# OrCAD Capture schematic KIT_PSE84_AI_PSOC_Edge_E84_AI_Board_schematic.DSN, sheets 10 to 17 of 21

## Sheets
10 09. On board sensors: size A4
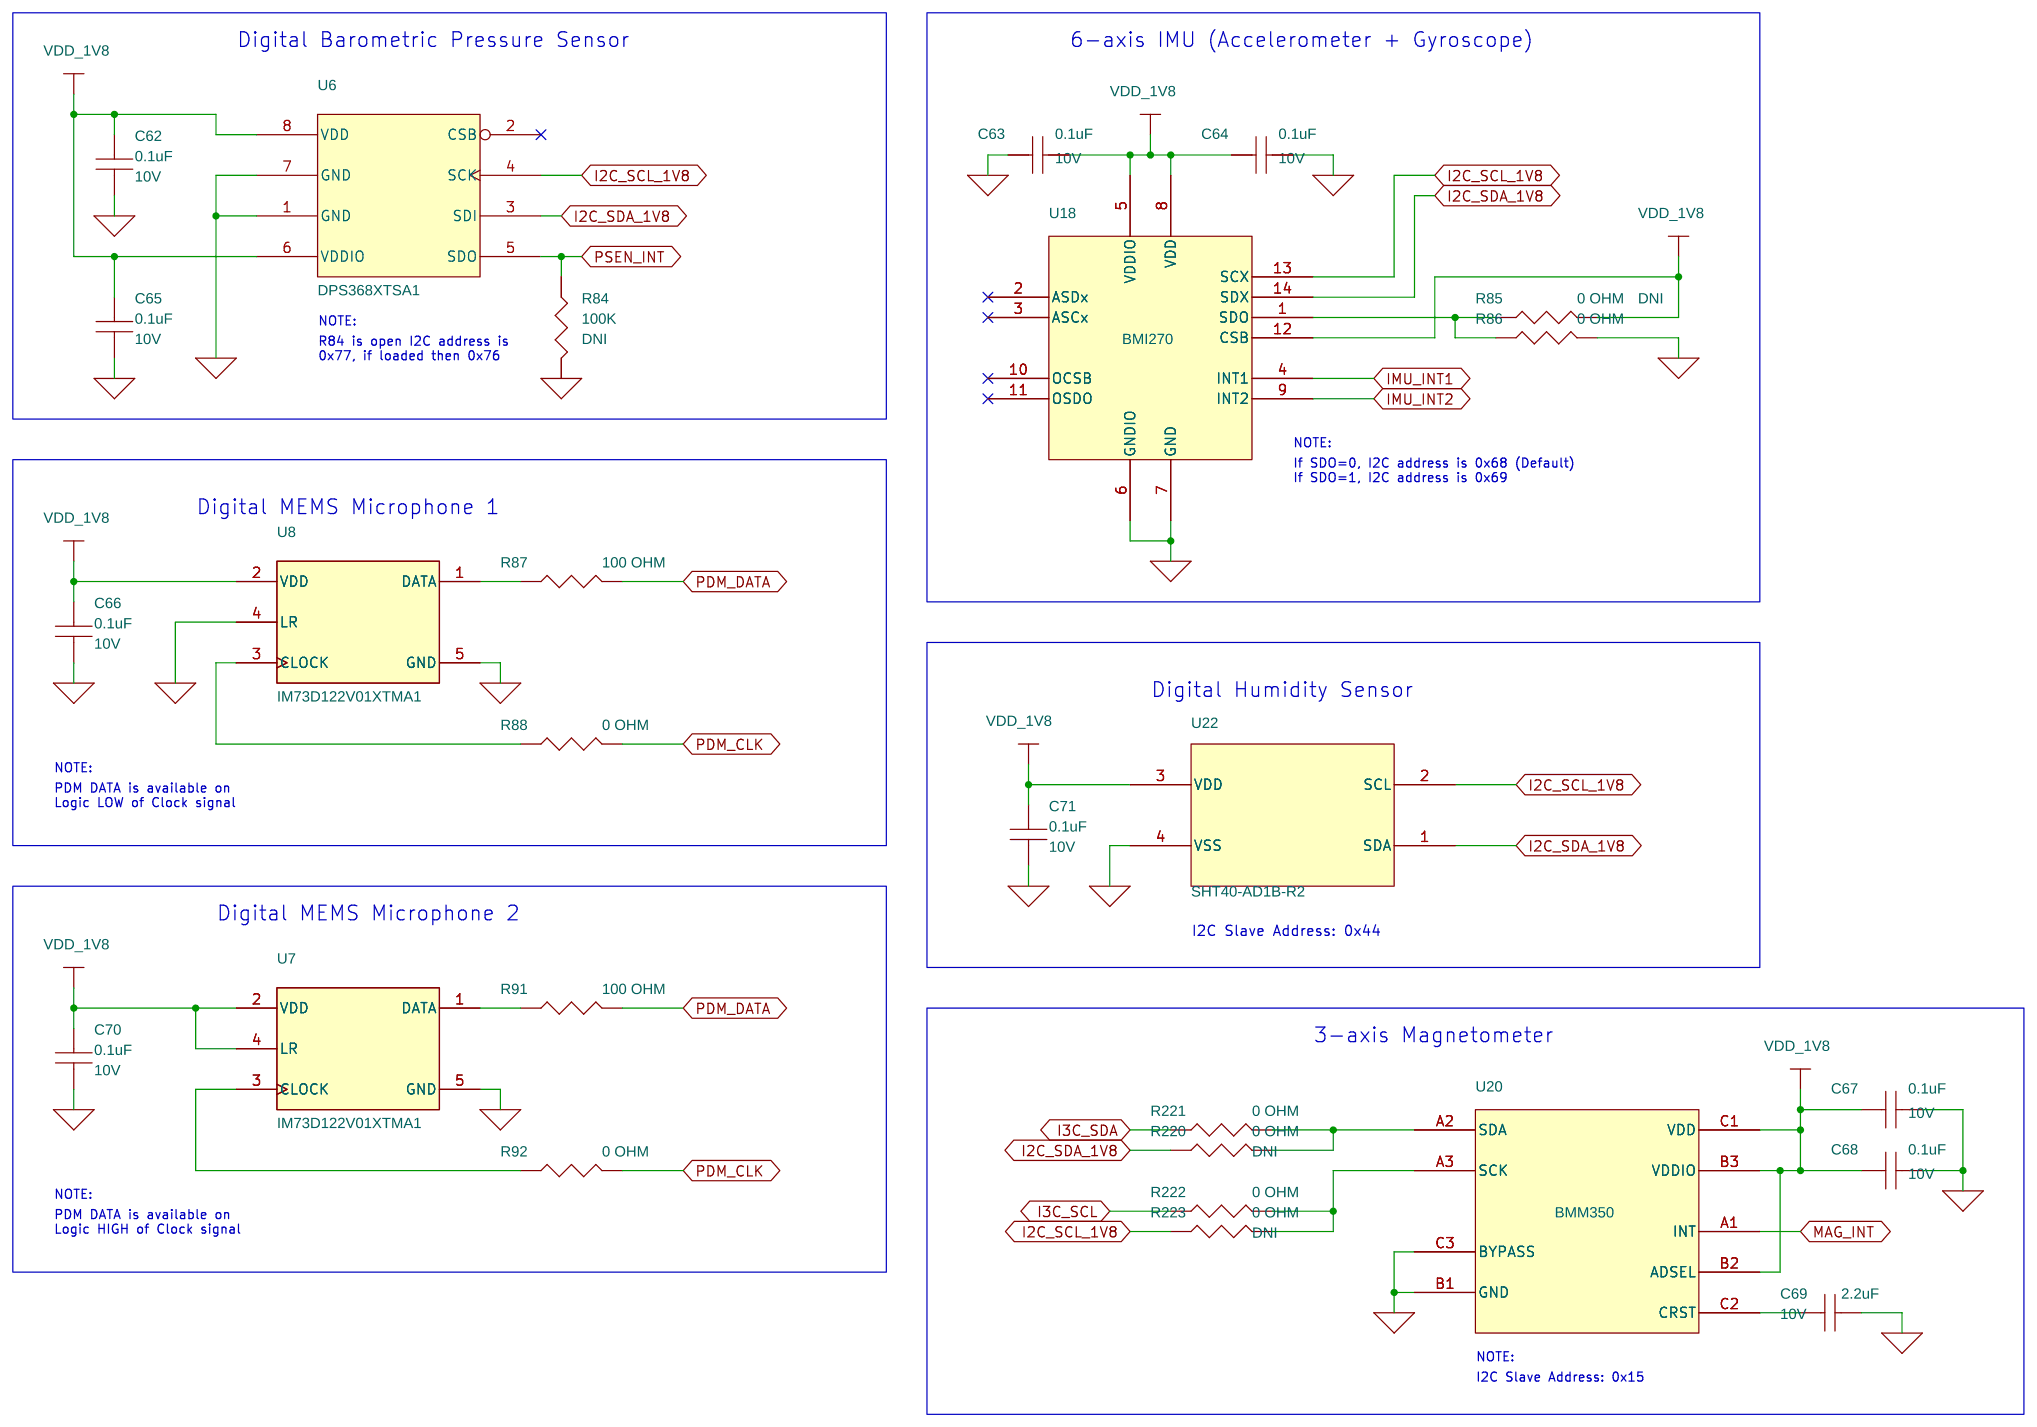
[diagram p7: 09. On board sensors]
11 10. RADAR Sensor interface: size A4
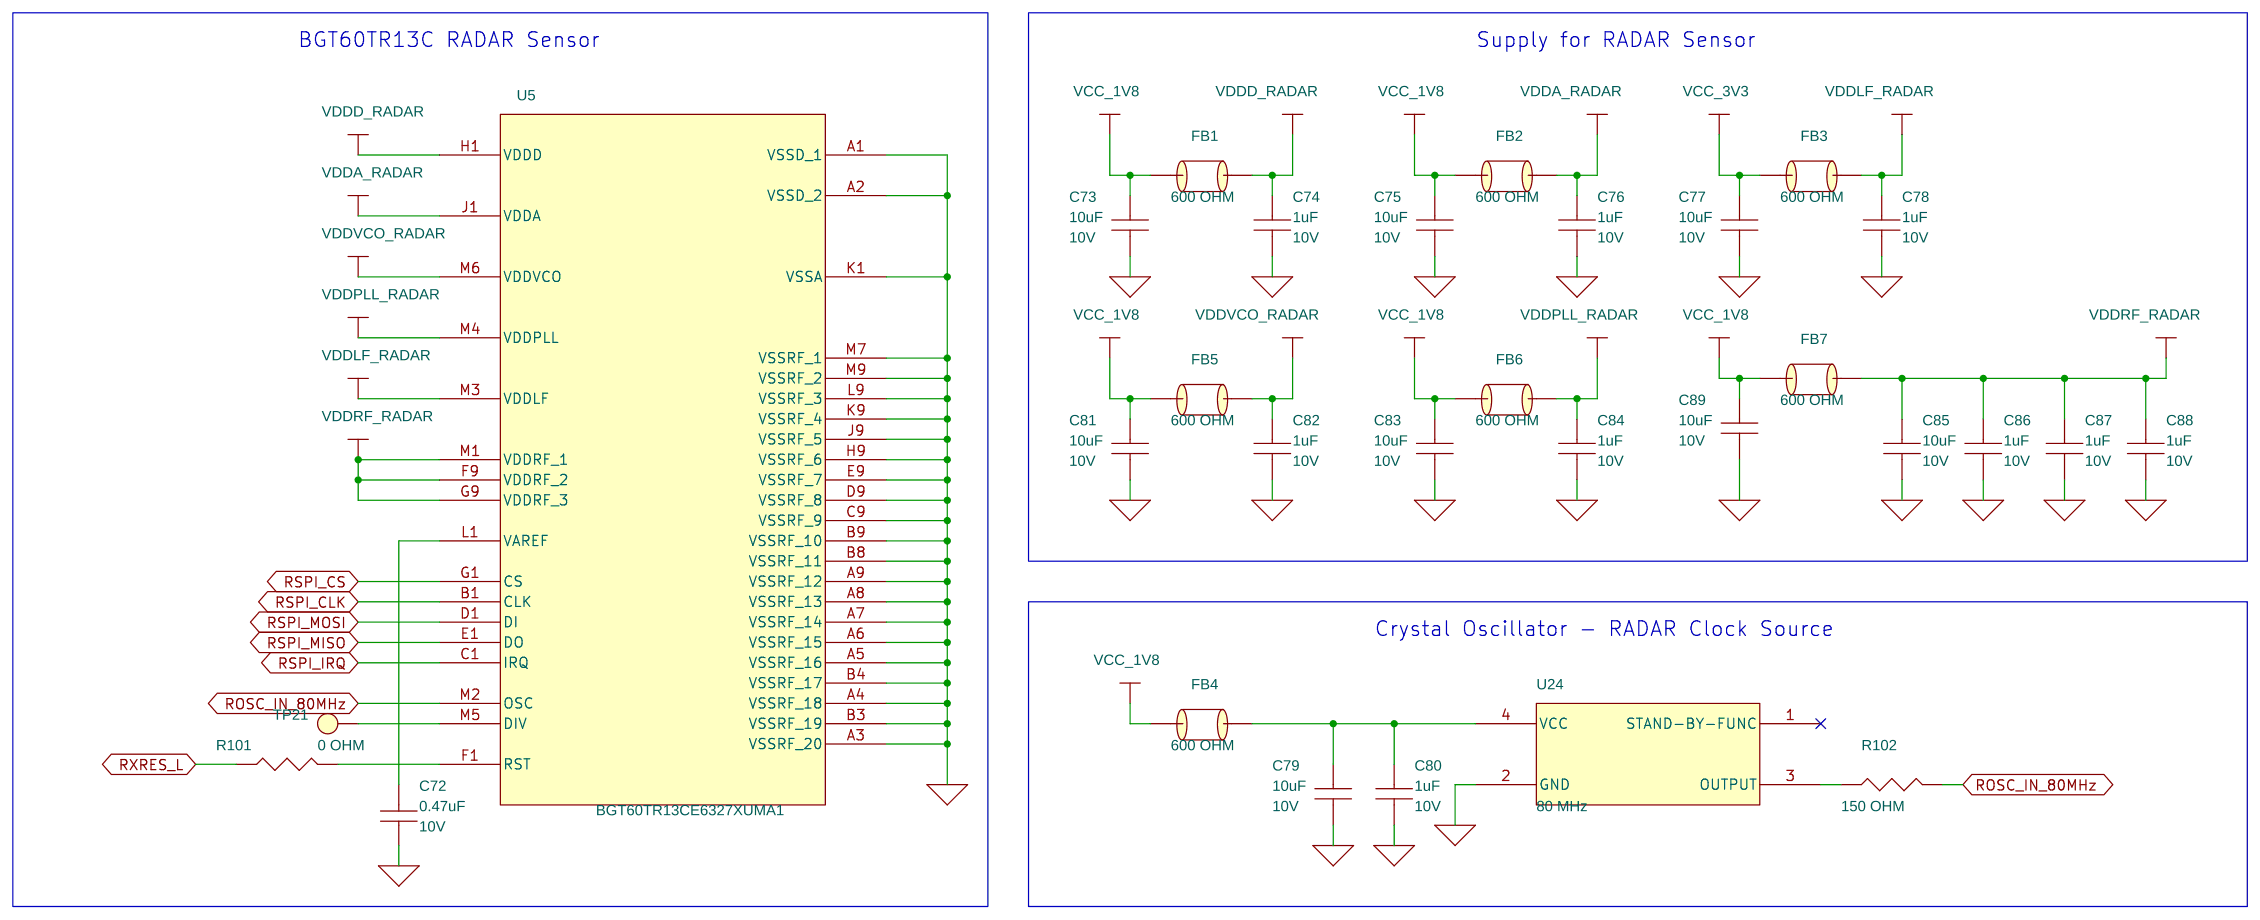
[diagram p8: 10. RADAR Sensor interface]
12 11. 2FY Module Interface: size A4
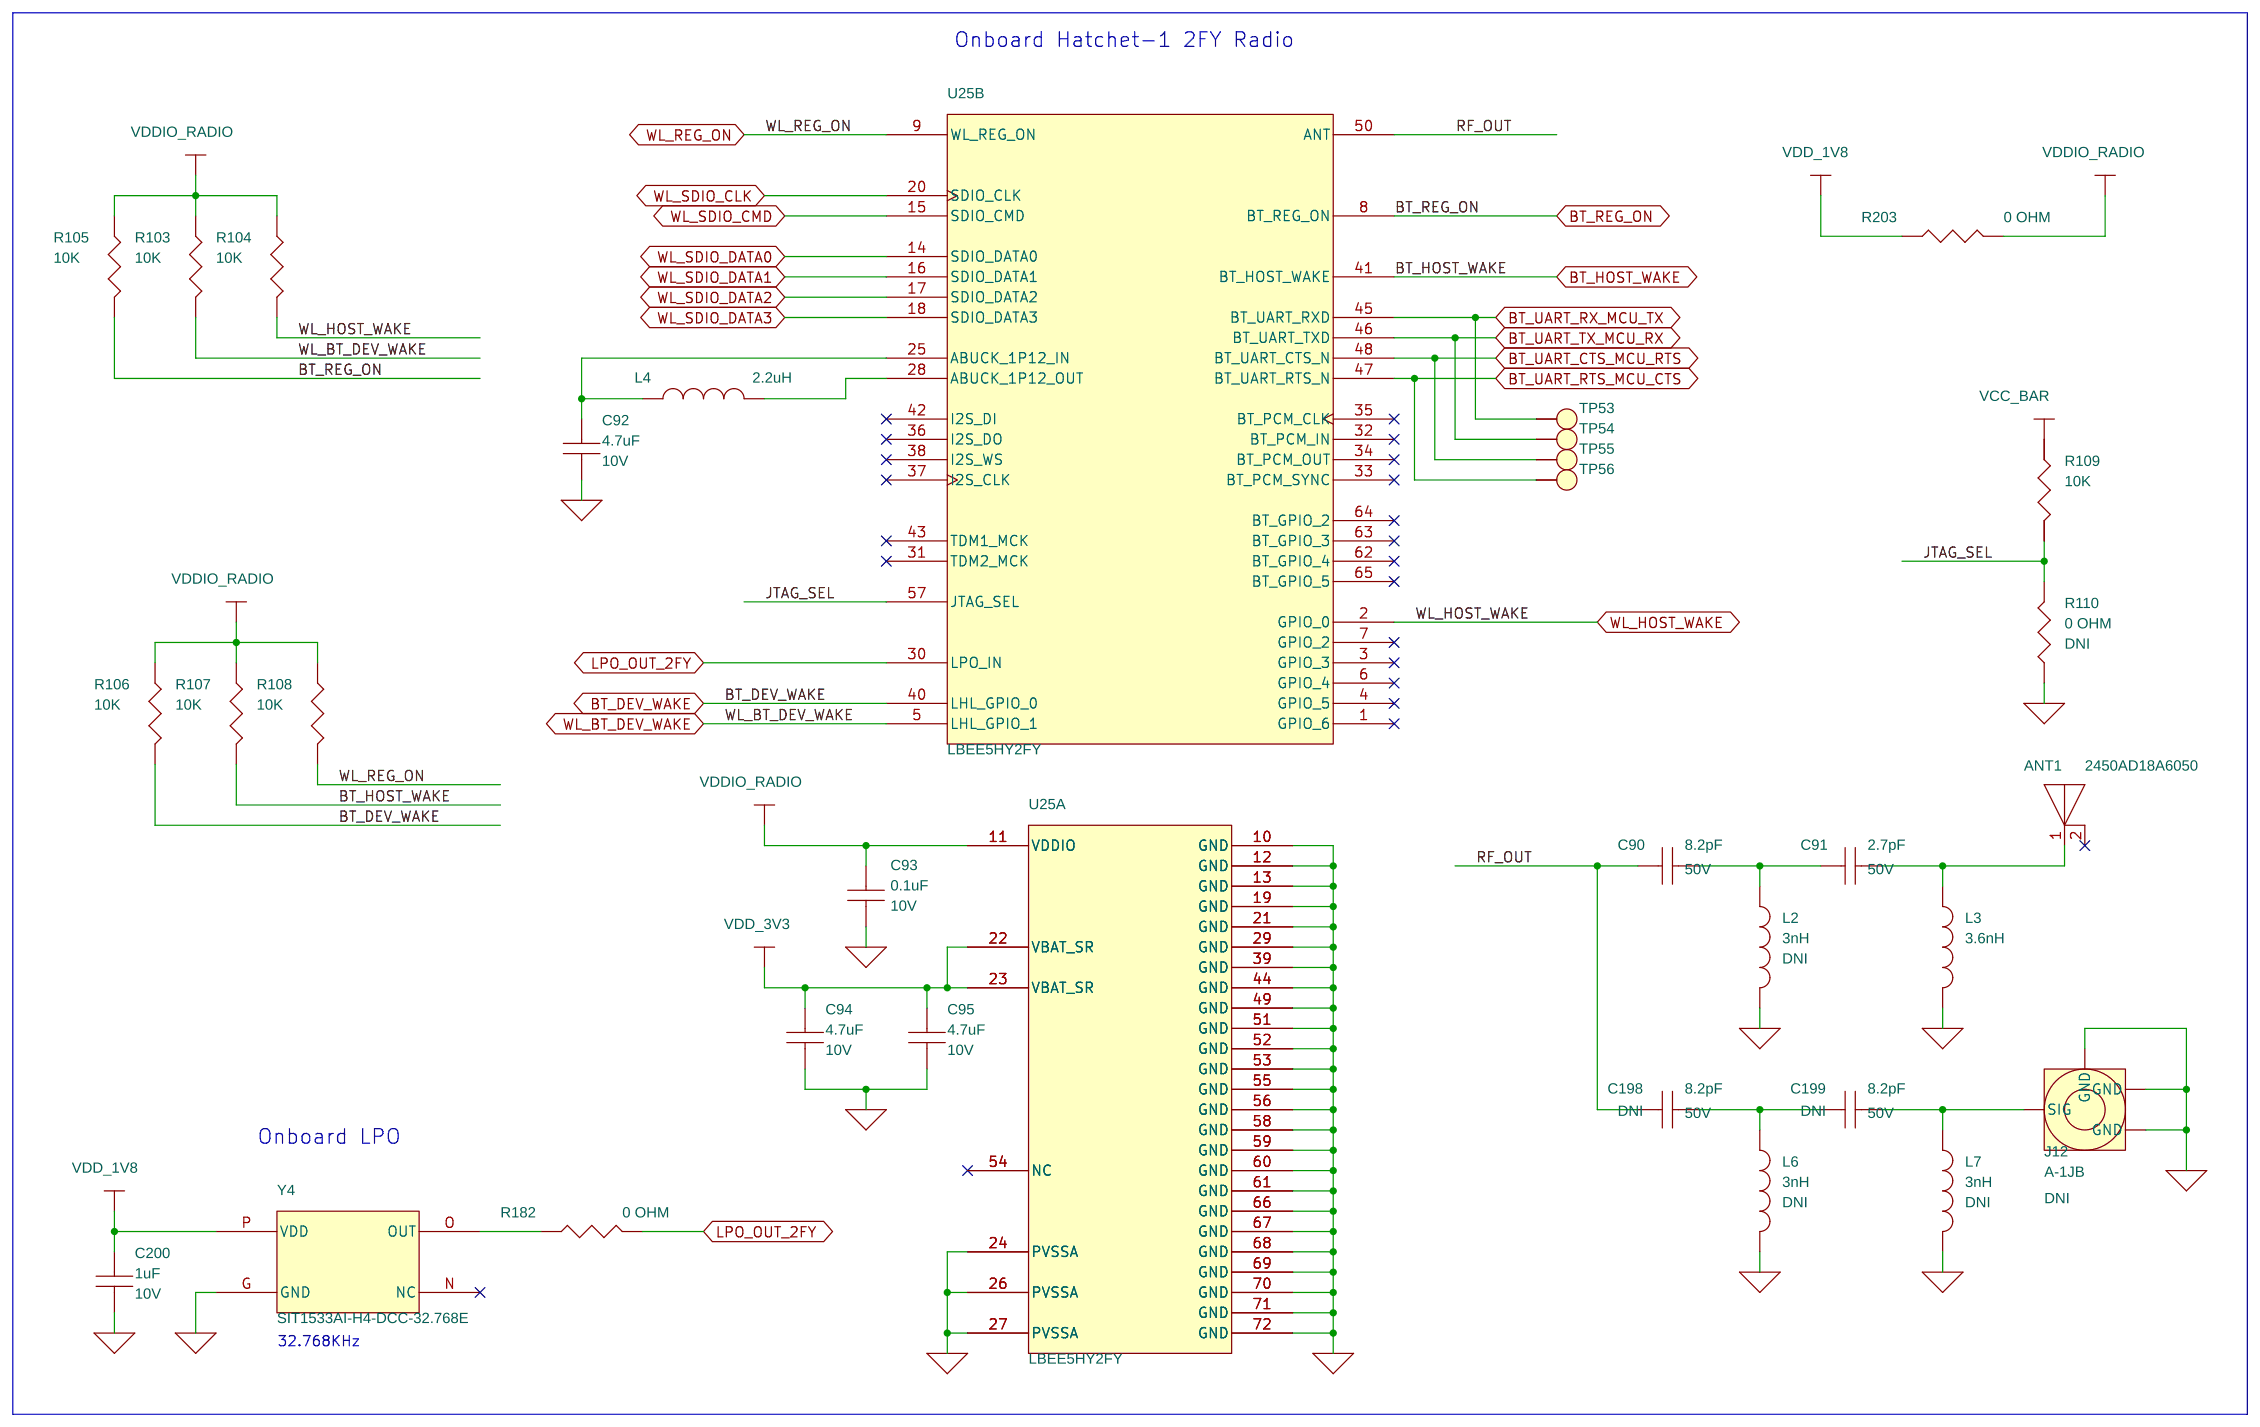
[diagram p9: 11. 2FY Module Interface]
13 12. IO Expansion connectors: size A4
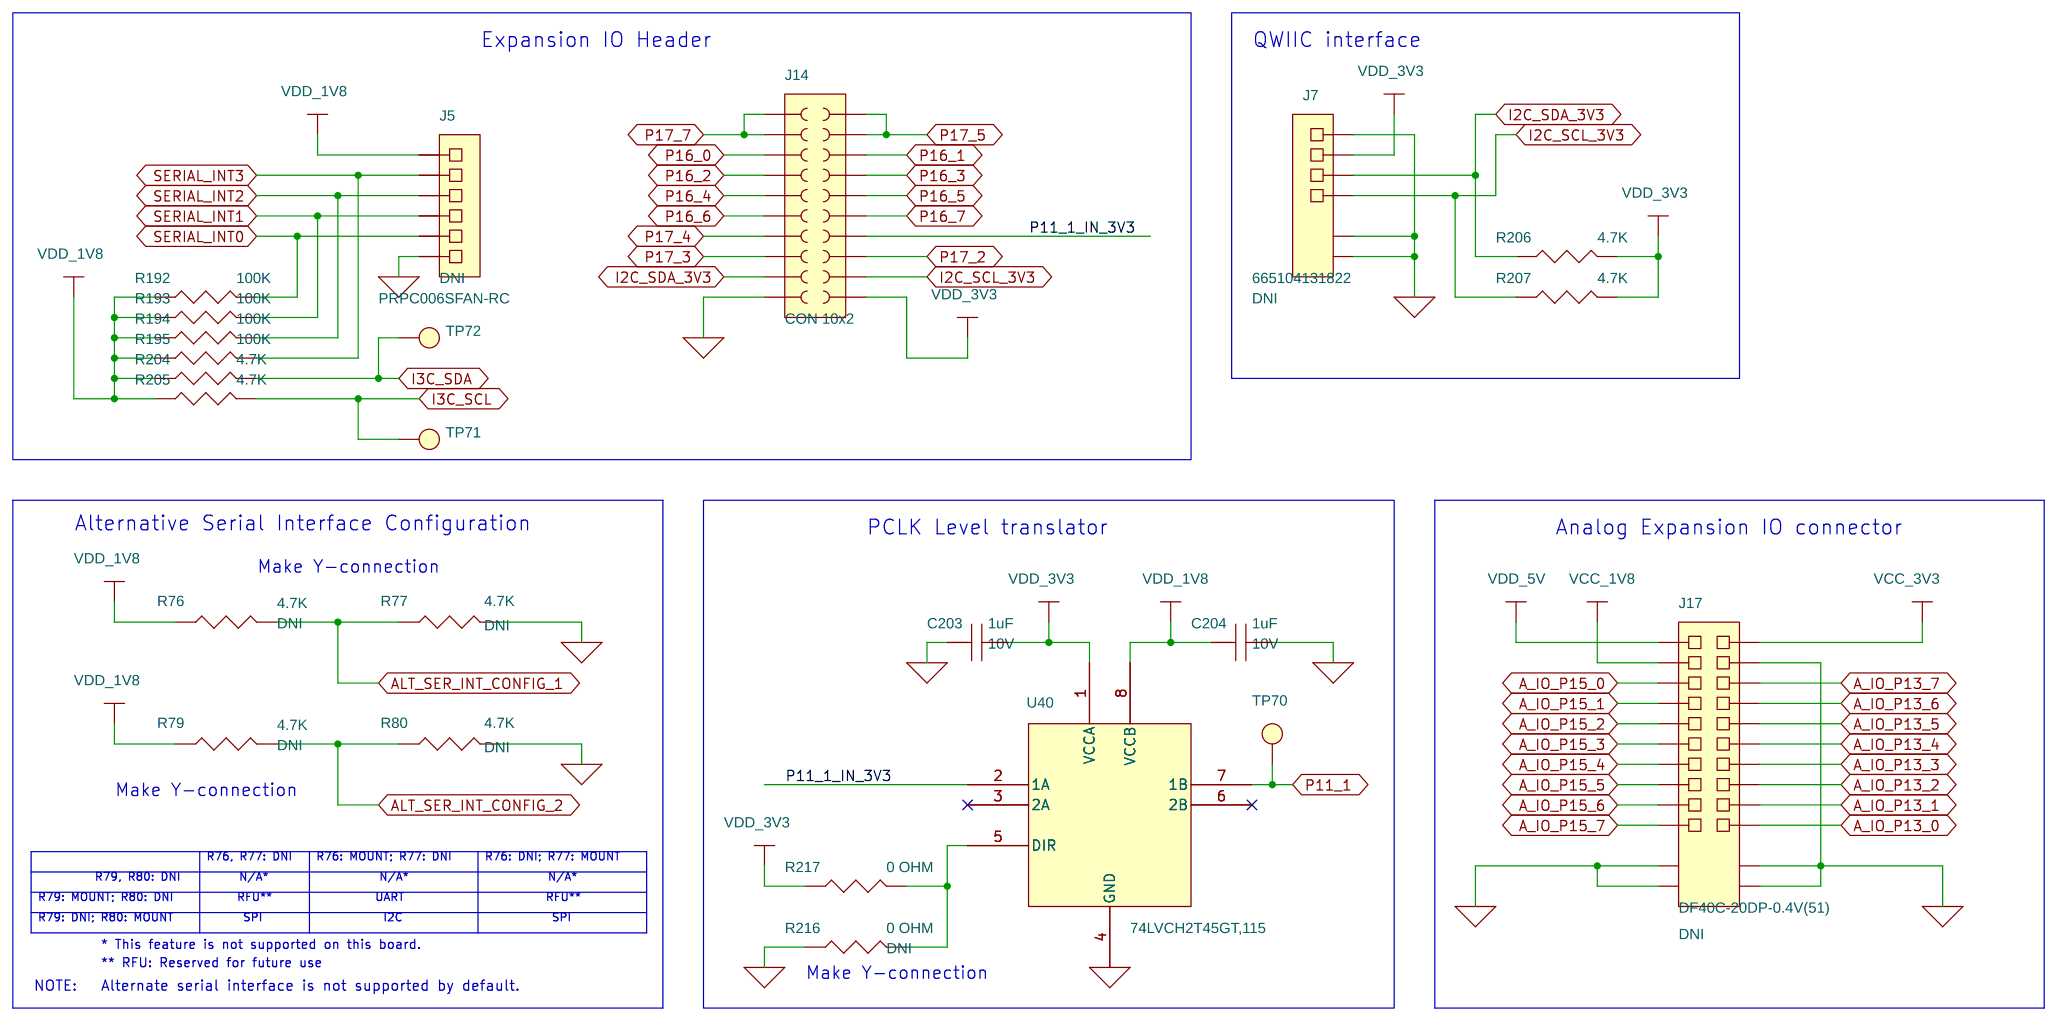
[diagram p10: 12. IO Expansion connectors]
14 13. Flash memory and RAM: size A4
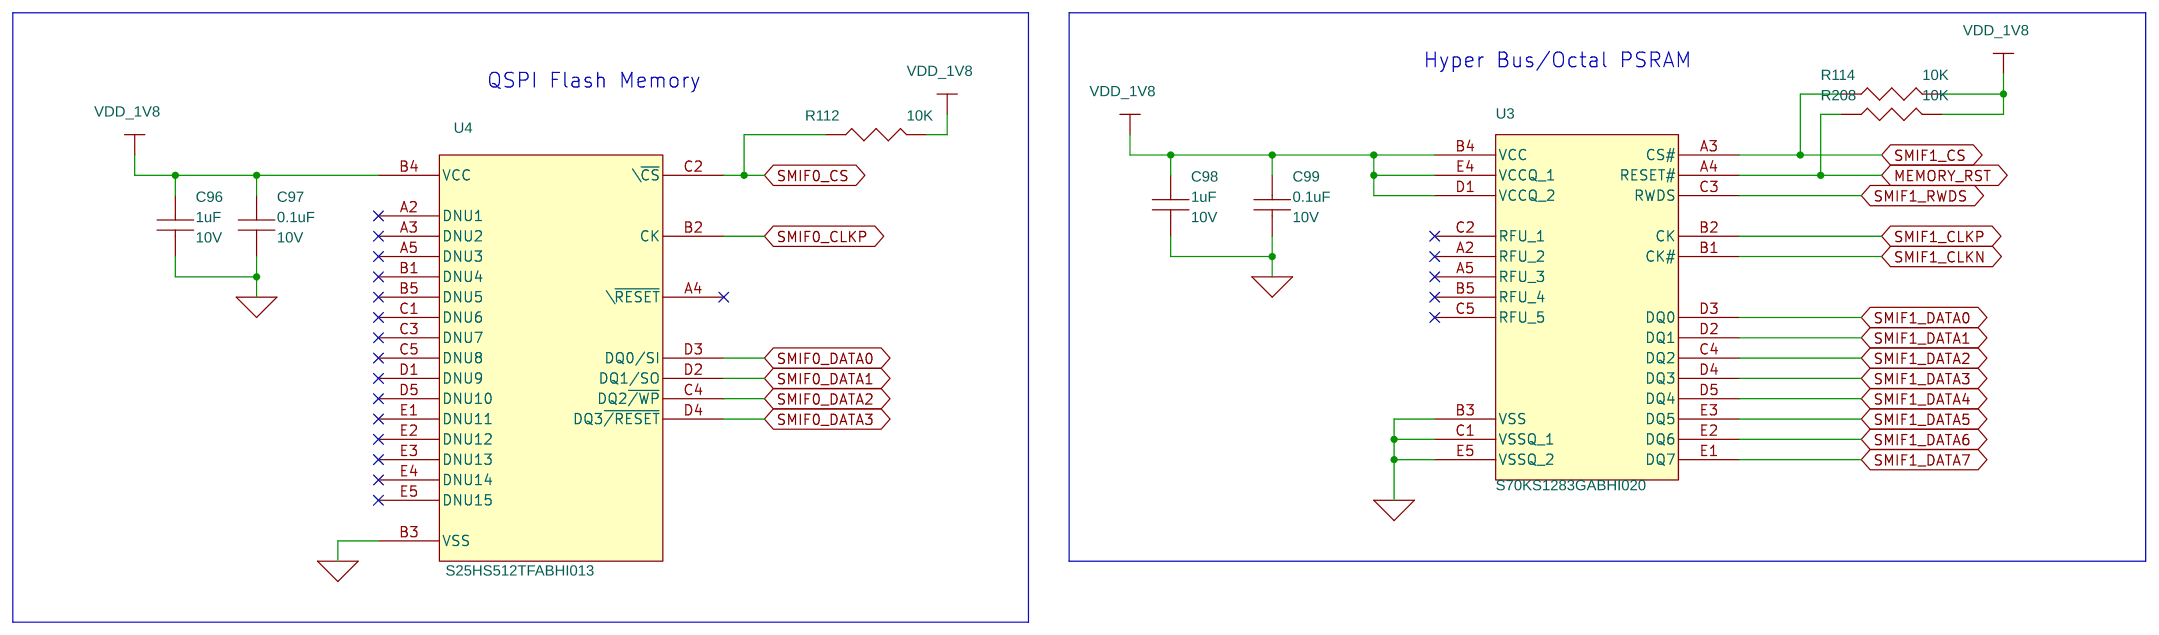
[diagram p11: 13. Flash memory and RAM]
15 14. Audio Class-D Amplifier: size A4
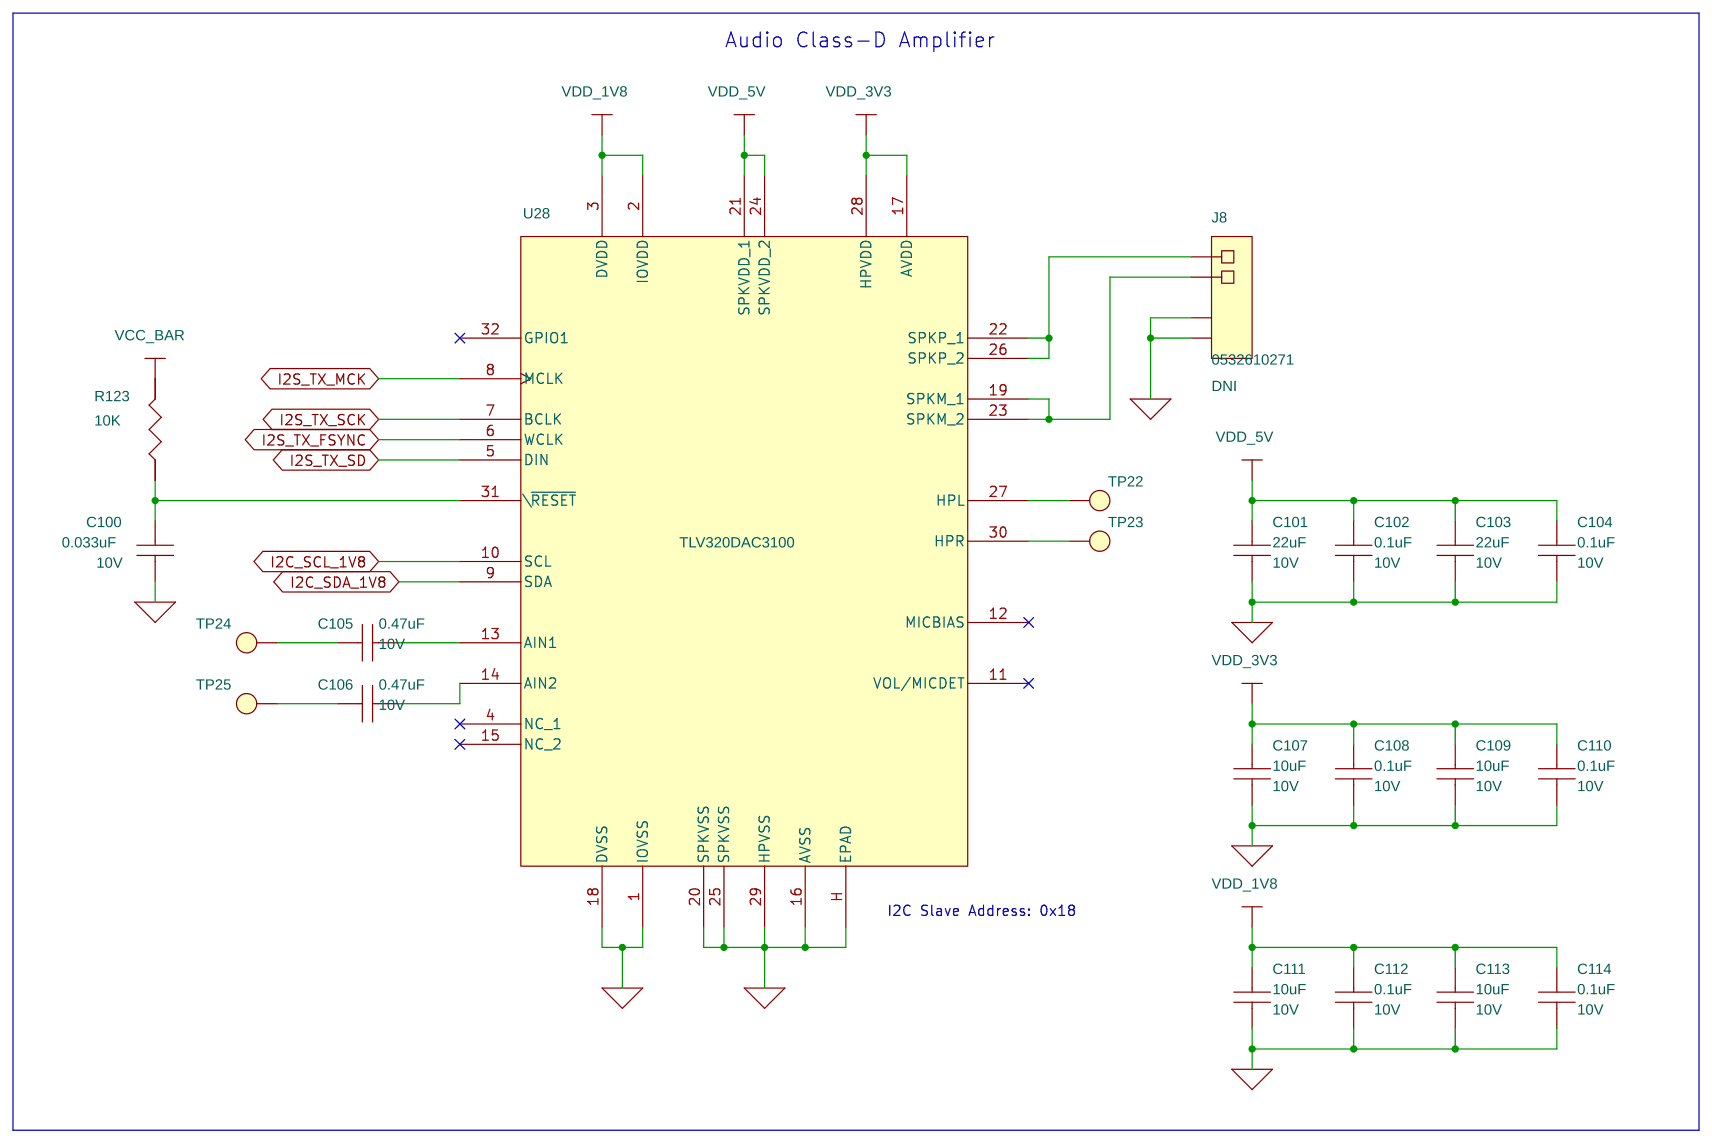
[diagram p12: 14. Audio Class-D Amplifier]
16 15. Analog Mic's: size A4
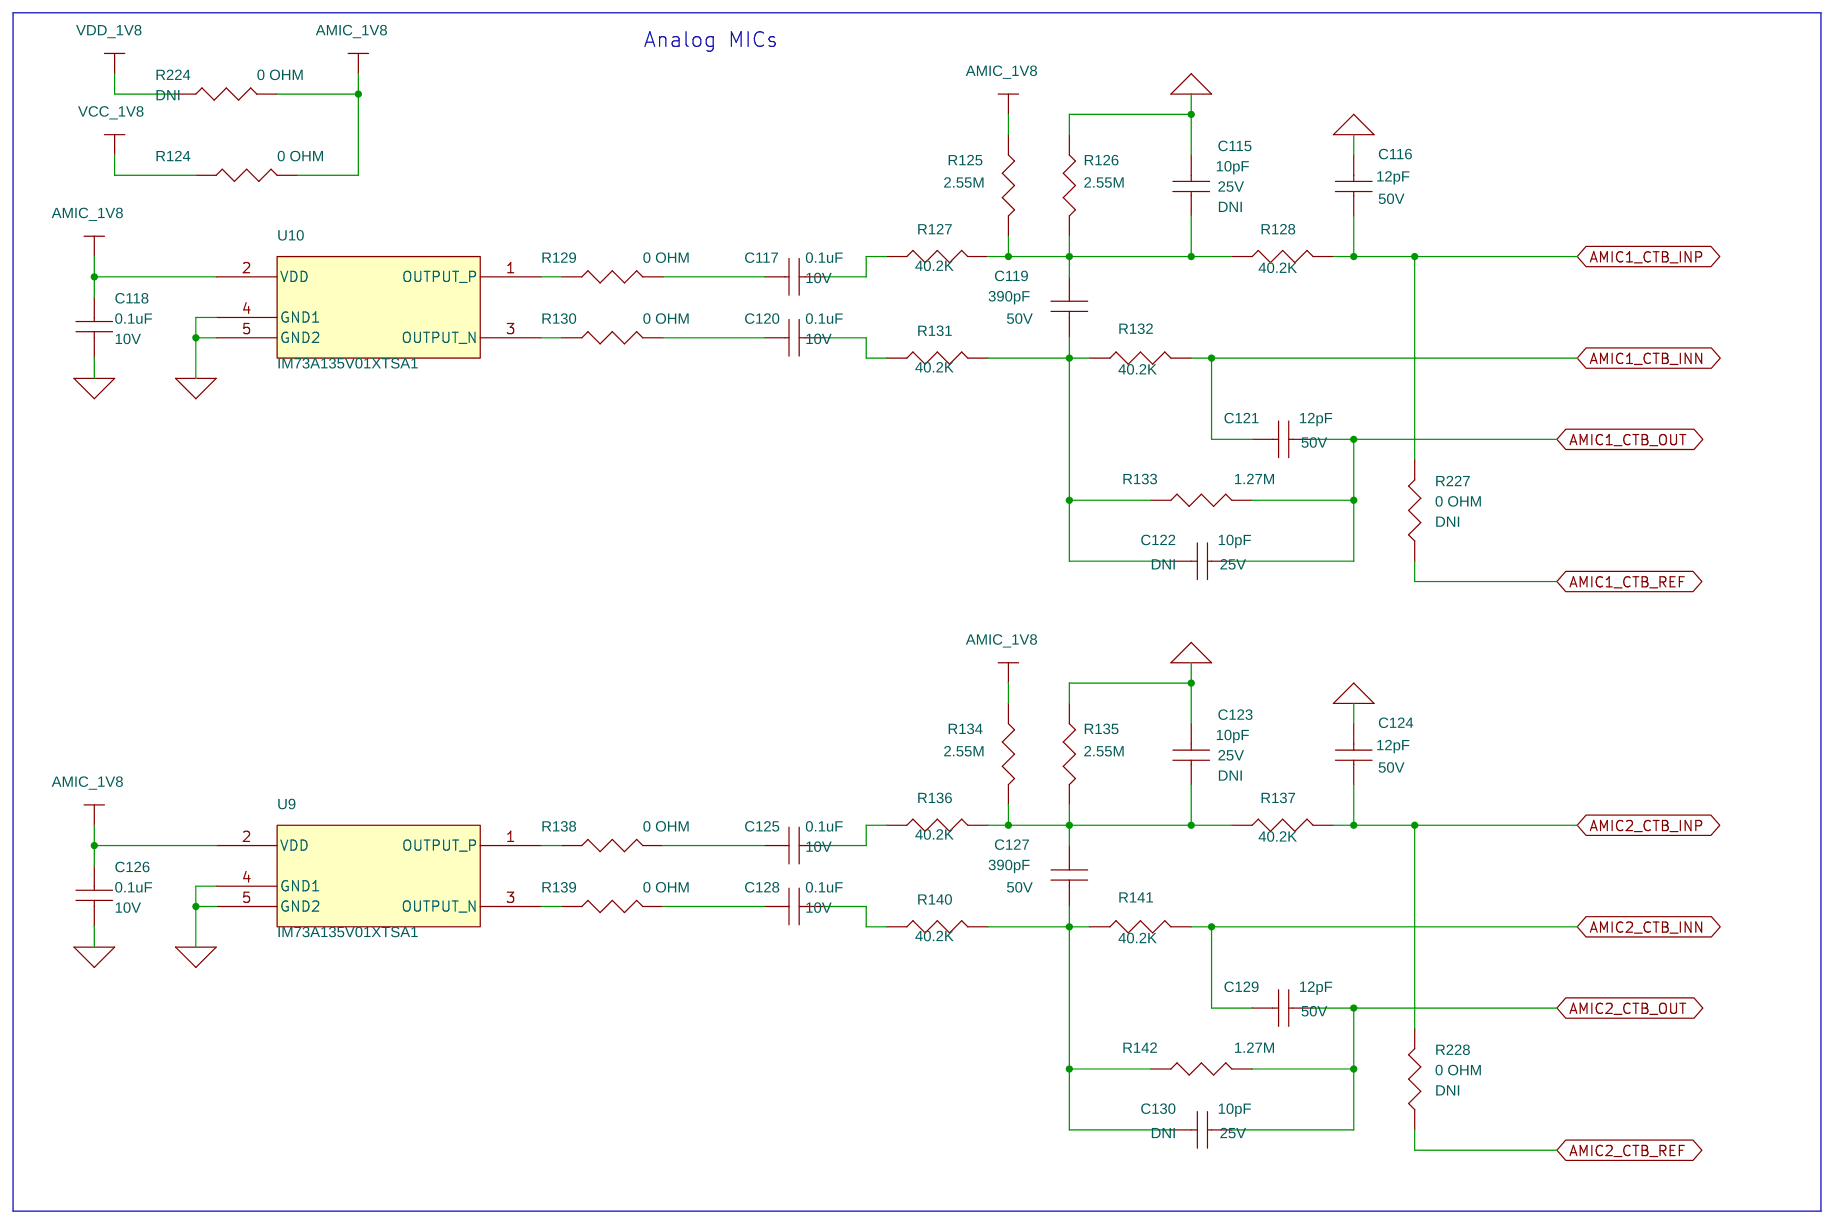
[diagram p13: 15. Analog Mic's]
17 16. MIPI-DSI Display Interface: size A4
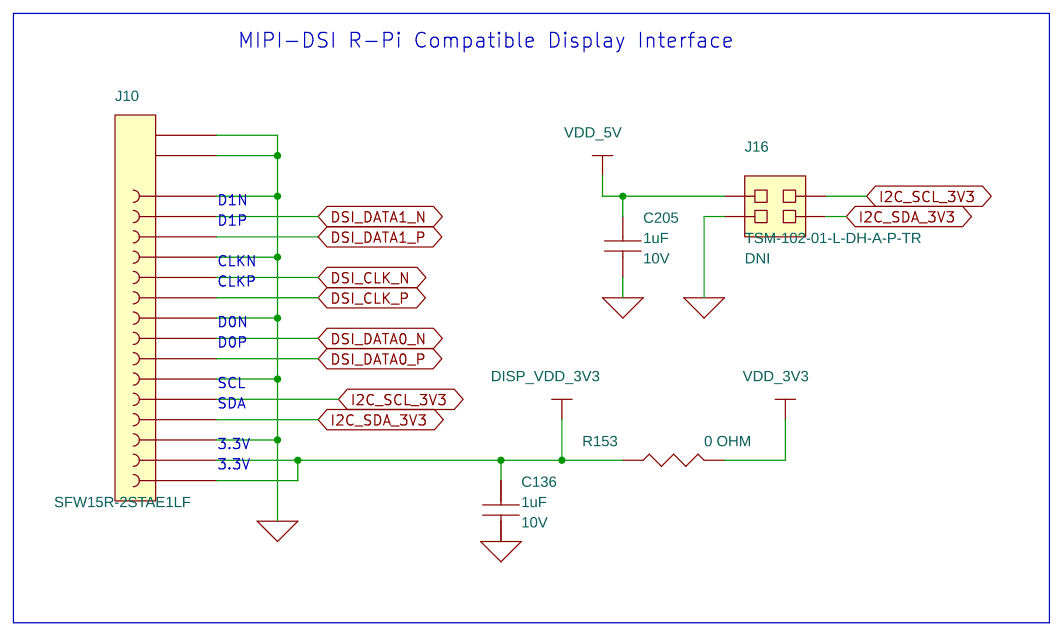
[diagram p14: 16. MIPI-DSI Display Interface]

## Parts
sheet 09. On board sensors
C62  0.1uF  [CAPC0603_0201N]
C63  0.1uF  [CAPC0603_0201N]
C64  0.1uF  [CAPC0603_0201N]
C65  0.1uF  [CAPC0603_0201N]
C66  0.1uF  [CAPC0603_0201N]
C67  0.1uF  [CAPC0603_0201N]
C68  0.1uF  [CAPC0603_0201N]
C69  2.2uF  [CAPC0603_0201N]
C70  0.1uF  [CAPC0603_0201N]
C71  0.1uF  [CAPC0603_0201N]
R84  100K  [RESC0603_0201N]
R85  0 OHM  [RESC0603_0201N]
R86  0 OHM  [RESC0603_0201N]
R87  100 OHM  [RESC0603_0201N]
R88  0 OHM  [RESC0603_0201N]
R91  100 OHM  [RESC0603_0201N]
R92  0 OHM  [RESC0603_0201N]
R220  0 OHM  [RESC1005_0402N]
R221  0 OHM  [RESC1005_0402N]
R222  0 OHM  [RESC1005_0402N]
R223  0 OHM  [RESC1005_0402N]
U6  DPS368XTSA1  [LGA8S145X65P2X4_200X250X110]
U7  IM73D122V01XTMA1  [MIC_IM73D122V01]
U8  IM73D122V01XTMA1  [MIC_IM73D122V01]
U18  BMI270  [BOSCH_BMI323]
U20  BMM350  [BOSCH_BMM350]
U22  SHT40-AD1B-R2  [SENSOR_SHT40-AD1B-R2]
sheet 10. RADAR Sensor interface
C72  0.47uF  [CAPC0603_0201N]
C73  10uF  [CAPC1005_0402N]
C74  1uF  [CAPC0603_0201N]
C75  10uF  [CAPC1005_0402N]
C76  1uF  [CAPC0603_0201N]
C77  10uF  [CAPC1005_0402N]
C78  1uF  [CAPC0603_0201N]
C79  10uF  [CAPC1005_0402N]
C80  1uF  [CAPC0603_0201N]
C81  10uF  [CAPC1005_0402N]
C82  1uF  [CAPC0603_0201N]
C83  10uF  [CAPC1005_0402N]
C84  1uF  [CAPC0603_0201N]
C85  10uF  [CAPC1005_0402N]
C86  1uF  [CAPC0603_0201N]
C87  1uF  [CAPC0603_0201N]
C88  1uF  [CAPC0603_0201N]
C89  10uF  [CAPC1005_0402N]
FB1  600 OHM  [INDC1005_0402M]
FB2  600 OHM  [INDC1005_0402M]
FB3  600 OHM  [INDC1005_0402M]
FB4  600 OHM  [INDC1005_0402M]
FB5  600 OHM  [INDC1005_0402M]
FB6  600 OHM  [INDC1005_0402M]
FB7  600 OHM  [INDC1005_0402M]
R101  0 OHM  [RESC0603_0201N]
R102  150 OHM  [RESC1005_0402N]
TP21  TP_SMD  [ict_tp_smd_030rd_nsp]
U5  BGT60TR13CE6327XUMA1  [VF2BGA40N50P9X12_500X650X90]
U24  80 MHz  [OSCCC200X160X80-4N]
sheet 11. 2FY Module Interface
ANT1  2450AD18A6050  [ANTENNA_2450AD18A6050]
C90  8.2pF  [CAPC1005_0402M]
C91  2.7pF  [CAPC1005_0402M]
C92  4.7uF  [CAPC1005_0402N]
C93  0.1uF  [CAPC0603_0201N]
C94  4.7uF  [CAPC1005_0402N]
C95  4.7uF  [CAPC1005_0402N]
C198  8.2pF  [CAPC1005_0402M]
C199  8.2pF  [CAPC1005_0402M]
C200  1uF  [CAPC1005_0402N]
J12  A-1JB  [AMP_A-1JB_ALT1]
L2  3nH  [INDC1005_0402M]
L3  3.6nH  [INDC1005_0402M]
L4  2.2uH  [IND_74479276222C]
L6  3nH  [INDC1005_0402M]
L7  3nH  [INDC1005_0402M]
R103  10K  [RESC0603_0201N]
R104  10K  [RESC0603_0201N]
R105  10K  [RESC0603_0201N]
R106  10K  [RESC0603_0201N]
R107  10K  [RESC0603_0201N]
R108  10K  [RESC0603_0201N]
R109  10K  [RESC0603_0201N]
R110  0 OHM  [RESC0603_0201N]
R182  0 OHM  [RESC1005_0402N]
R203  0 OHM  [RESC1005_0402N]
TP53  TP_SMD  [ict_tp_smd_030rd_nsp]
TP54  TP_SMD  [ict_tp_smd_030rd_nsp]
TP55  TP_SMD  [ict_tp_smd_030rd_nsp]
TP56  TP_SMD  [ict_tp_smd_030rd_nsp]
U25  LBEE5HY2FY  [MODULE_LBEE5HY2FY]  (sections A,B)
Y4  SIT1533AI-H4-DCC-32.768E  [OSCS4_SIT_2M0X1M2SPL_NGOPQ]
sheet 12. IO Expansion connectors
C203  1uF  [CAPC1005_0402N]
C204  1uF  [CAPC1005_0402N]
J5  PRPC006SFAN-RC  [SULLINS_PRPC006SFAN-RC]
J7  665104131822  [JST_SM04B-SRSS-TB]
J14  CON 10x2  [RTST254P2X10_W515]
J17  DF40C-20DP-0.4V(51)  [HIROSE_DF40C-20DP-0P4V]
R76  4.7K  [RESC1608_0603M]
R77  4.7K  [RESC1608_0603M]
R79  4.7K  [RESC1608_0603M]
R80  4.7K  [RESC1608_0603M]
R192  100K  [RESC0603_0201N]
R193  100K  [RESC0603_0201N]
R194  100K  [RESC0603_0201N]
R195  100K  [RESC0603_0201N]
R204  4.7K  [RESC0603_0201N]
R205  4.7K  [RESC0603_0201N]
R206  4.7K  [RESC0603_0201N]
R207  4.7K  [RESC0603_0201N]
R216  0 OHM  [RESC1005_0402N]
R217  0 OHM  [RESC1005_0402N]
TP70  TP_SMD  [ict_tp_smd_030rd_nsp]
TP71  TP_SMD  [ict_tp_smd_030rd_nsp]
TP72  TP_SMD  [ict_tp_smd_030rd_nsp]
U40  74LVCH2T45GT,115  [SON50P100X200_08_SOT833-1]
sheet 13. Flash memory and RAM
C96  1uF  [CAPC0603_0201N]
C97  0.1uF  [CAPC0603_0201N]
C98  1uF  [CAPC0603_0201N]
C99  0.1uF  [CAPC0603_0201N]
R112  10K  [RESC0603_0201N]
R114  10K  [RESC0603_0201N]
R208  10K  [RESC0603_0201N]
U3  S70KS1283GABHI020  [BGA24C100P5x5_600x800x120]
U4  S25HS512TFABHI013  [BGA24C100P5X5_600X800X120]
sheet 14. Audio Class-D Amplifier
C100  0.033uF  [CAPC1005_0402N]
C101  22uF  [CAPC1005_0402N]
C102  0.1uF  [CAPC0603_0201N]
C103  22uF  [CAPC1005_0402N]
C104  0.1uF  [CAPC0603_0201N]
C105  0.47uF  [CAPC0603_0201N]
C106  0.47uF  [CAPC0603_0201N]
C107  10uF  [CAPC1005_0402N]
C108  0.1uF  [CAPC0603_0201N]
C109  10uF  [CAPC1005_0402N]
C110  0.1uF  [CAPC0603_0201N]
C111  10uF  [CAPC1005_0402N]
C112  0.1uF  [CAPC0603_0201N]
C113  10uF  [CAPC1005_0402N]
C114  0.1uF  [CAPC0603_0201N]
J8  0532610271  [MOLEX_532610271]
R123  10K  [RESC0603_0201N]
TP22  TP_SMD  [ict_tp_smd_030rd_nsp]
TP23  TP_SMD  [ict_tp_smd_030rd_nsp]
TP24  TP_SMD  [ict_tp_smd_030rd_nsp]
TP25  TP_SMD  [ict_tp_smd_030rd_nsp]
U28  TLV320DAC3100  [QFN50P500X500X100-32N_TP_NOFID]
sheet 15. Analog Mic's
C115  10pF  [CAPC0603_0201N]
C116  12pF  [CAPC0603_0201N]
C117  0.1uF  [CAPC0603_0201N]
C118  0.1uF  [CAPC0603_0201N]
C119  390pF  [CAPC0603_0201N]
C120  0.1uF  [CAPC0603_0201N]
C121  12pF  [CAPC0603_0201N]
C122  10pF  [CAPC0603_0201N]
C123  10pF  [CAPC0603_0201N]
C124  12pF  [CAPC0603_0201N]
C125  0.1uF  [CAPC0603_0201N]
C126  0.1uF  [CAPC0603_0201N]
C127  390pF  [CAPC0603_0201N]
C128  0.1uF  [CAPC0603_0201N]
C129  12pF  [CAPC0603_0201N]
C130  10pF  [CAPC0603_0201N]
R124  0 OHM  [RESC1005_0402N]
R125  2.55M  [RESC0603_0201N]
R126  2.55M  [RESC0603_0201N]
R127  40.2K  [RESC0603_0201N]
R128  40.2K  [RESC0603_0201N]
R129  0 OHM  [RESC0603_0201N]
R130  0 OHM  [RESC0603_0201N]
R131  40.2K  [RESC0603_0201N]
R132  40.2K  [RESC0603_0201N]
R133  1.27M  [RESC0603_0201N]
R134  2.55M  [RESC0603_0201N]
R135  2.55M  [RESC0603_0201N]
R136  40.2K  [RESC0603_0201N]
R137  40.2K  [RESC0603_0201N]
R138  0 OHM  [RESC0603_0201N]
R139  0 OHM  [RESC0603_0201N]
R140  40.2K  [RESC0603_0201N]
R141  40.2K  [RESC0603_0201N]
R142  1.27M  [RESC0603_0201N]
R224  0 OHM  [RESC1005_0402N]
R227  0 OHM  [RESC1005_0402N]
R228  0 OHM  [RESC1005_0402N]
U9  IM73A135V01XTSA1  [MIC_IM73A135V01XTSA1]
U10  IM73A135V01XTSA1  [MIC_IM73A135V01XTSA1]
sheet 16. MIPI-DSI Display Interface
C136  1uF  [CAPC0603_0201N]
C205  1uF  [CAPC0603_0201N]
J10  SFW15R-2STAE1LF  [AMPHENOL_SFW15R-2STAE1LF]
J16  TSM-102-01-L-DH-A-P-TR  [SAMTEC_TSM-102-01-L-DH-A-P-TR]
R153  0 OHM  [RESC1005_0402N]

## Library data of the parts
C62-C68 C70 C71 C93 C97 C99 C102 C104 C108 C110 C112 C114 C117 C118 C120 C125 C126 C128 = CAP-NP: CAP, CER, 0.1uF, 10%, X5R, 10V, 0201; Approved: Approved; CY_PN: 510-60777-01; Device_File: 510-60777-01; Dielectric: X5R; FPLIST: CAPC0603_0201N,CAPC0603_0201Q; Lifecycle: Active; Manufacturer: Wurth; Manufacturer_PN: 885012104002; Operating_Temp: -55°C ~ 85°C; Package: 0201; Part_Status: In Prod; Tolerance: 0.1; Voltage: 10V
C69 = CAP-NP: CAP, CER, 0201, 2.2uF, 10%, 10V, X5R; Approved: Approved; CY_PN: 510-60962-01; Device_File: 510-60962-01; Dielectric: X5R; FPLIST: CAPC0603_0201N,CAPC0603_0201Q; Lifecycle: Active; Manufacturer: Murata; Manufacturer_PN: GRM033R61A225KE47D; Operating_Temp: -55°C ~ 85°C; Package: 0201; Part_Status: In Des; Tolerance: 10%; Voltage: 10V
R84 = RES: RES, 100K OHM, 1%, 1/20W, 0201; Approved: Approved; CY_PN: 500-61334-01; DNI: DNI; Device File: 500-60429-01; Device_File: 500-61334-01; FPLIST: RESC0603_0201N,RESC0603_0201Q; Lifecycle: Active; Manufacturer: Yageo; Manufacturer_PN: RC0201FR-07100KL; Operating_Temp: -55°C ~ 125°C; Package: 0201; Part_Status: Unrel; Rating: 1/20W; Tolerance: 1%
R85 R110 = RES: RES, Fixed, 0 OHM, JUMPER, 1/20W, 0201; Approved: Approved; CY_PN: 500-60684-01; DNI: DNI; Device File: 500-60037-01; Device_File: 500-60684-01; FPLIST: RESC0603_0201N,RESC0603_0201Q; Lifecycle: Active; Manufacturer: Panasonic; Manufacturer_PN: ERJ-1GN0R00C; Operating_Temp: -55°C ~ 125°C; Package: 0201; Part_Status: In Prod; Rating: 1/20W; Tolerance: JUMPER
R86 R88 R92 R101 R129 R130 R138 R139 = RES: RES, Fixed, 0 OHM, JUMPER, 1/20W, 0201; Approved: Approved; CY_PN: 500-60684-01; Device File: 500-60037-01; Device_File: 500-60684-01; FPLIST: RESC0603_0201N,RESC0603_0201Q; Lifecycle: Active; Manufacturer: Panasonic; Manufacturer_PN: ERJ-1GN0R00C; Operating_Temp: -55°C ~ 125°C; Package: 0201; Part_Status: In Prod; Rating: 1/20W; Tolerance: JUMPER
R87 R91 = RES: RES, FIXED, 100 OHM, 5%, 1/20W, 0201; Approved: Approved; CY_PN: 500-61324-01; Device File: 500-60384-01; Device_File: 500-61324-01; FPLIST: RESC0603_0201N,RESC0603_0201Q; Lifecycle: Active; Manufacturer: Yageo; Manufacturer_PN: RC0201JR-07100RL; Operating_Temp: -55°C ~ 125°C; Package: 0201; Part_Status: Unrel; Rating: 1/20W; Tolerance: 5%
R216 R220 R223 = RES: RES, FIXED, 0 OHM, JUMPER, 1A, 1/16W, 0402; Approved: Approved; CY_PN: 500-60344-01; DNI: DNI; Device File: 500-60037-01; Device_File: 500-60344-01; FPLIST: RESC1005_0402N,RESC1005_0402M; Lifecycle: Active; Manufacturer: Wurth; Manufacturer_PN: 560112110001; Operating_Temp: -55°C ~ 155°C; Package: 0402; Part_Status: In Prod; Rating: 1/16W; Tolerance: JUMPER
R203 R217 R221 R222 = RES: RES, FIXED, 0 OHM, JUMPER, 1A, 1/16W, 0402; Approved: Approved; CY_PN: 500-60344-01; Device File: 500-60037-01; Device_File: 500-60344-01; FPLIST: RESC1005_0402N,RESC1005_0402M; Lifecycle: Active; Manufacturer: Wurth; Manufacturer_PN: 560112110001; Operating_Temp: -55°C ~ 155°C; Package: 0402; Part_Status: In Prod; Rating: 1/16W; Tolerance: JUMPER
U6 = IC_DPS368: IC, INFINEON, SENSOR, 17.4PSIG, 24BIT, 8VLGA; Approved: Approved; Lifecycle: Active; Manufacturer: infineon; Operating_Temp: -40°C ~ 85°C; Operating_Voltage: 1.7V ~ 3.6V; Package: 8VLGA; Part_Status: Unrel
U7 U8 = IC_IM73D122V01: IC, Infineon, Digital MEMS Microphone, 1.62V to 3.6V, -26dB, SMD; Approved: Approved; Lifecycle: Active; Manufacturer: Infineon; Operating_Temp: -40°C ~ 85°C; Operating_Voltage: 1.62V ~  3.6V; Package: PG-LLGA-5-3; Part_Status: Unrel
U18 = IC_BMI270: IC, IMU, ACCELEROMETER/GYRO, 6-AXIS, I2C/SPI, 14-LGA; Approved: Approved; CY_PN: 415-00031-01; Device_File: 415-00031-01; Lifecycle: Active; Manufacturer: Bosch; Operating_Temp: -40°C to 85°C; Operating_Voltage: 1.71V~3.6V, 1.2V~3.6V; Package: 14-LGA; Part_Status: Unrel
U20 = IC_BMM350: IC, SENSOR, MAGNETOMETER, MAGNETORESISTIVE, 3-AXIS, I2C/I3C, 9-WLCSP; Approved: Approved; CY_PN: 415-00032-01; Device_File: 415-00032-01; Lifecycle: Active; Manufacturer: Bosch; Operating_Temp: -40°C to 85°C; Operating_Voltage: 1.72V~1.98V, 1.72V~3.6V; Package: 9-WLCSP; Part_Status: Unrel
U22 = IC_SHT40-AD1B-R2: IC, SENSOR HUMIDITY, 100 RH, SMD; Approved: Approved; CY_PN: 415-00035-01; Device_File: 415-00035-01; Lifecycle: Active; Manufacturer: SENSIRION; Operating_Temp: -40°C ~ 125°C; Operating_Voltage: 1.08V ~ 3.6V; Package: SMD; Part_Status: Unrel
C72 C105 C106 = CAP-NP: CAP, CER, 0.47uF, 20%, 10V, X5R, 0201; Approved: Approved; CY_PN: 510-61117-01; Device_File: 510-61117-01; Dielectric: X5R; FPLIST: CAPC0603_0201N,CAPC0603_0201Q; Lifecycle: Active; Manufacturer: TDK Corporation; Manufacturer_PN: C0603X5R1A474M030BC; Operating_Temp: -55°C ~ 85°C; Package: 0201; Part_Status: Unrel; Tolerance: 20%; Voltage: 10V
C73 C75 C77 C79 C81 C83 C85 C89 C107 C109 C111 C113 = CAP-NP: CAP, CER, 10uF, 20%, X5R, 10V, 0402; Approved: Approved; CY_PN: 510-60337-01; Device_File: 510-60337-01; Dielectric: X5R; FPLIST: CAPC1005_0402N,CAPC1005_0402M; Lifecycle: Active; Manufacturer: Wurth; Manufacturer_PN: 885012105022; Operating_Temp: -55°C ~ 85°C; Package: 0402; Part_Status: Unrel; Tolerance: 20%; Voltage: 10V
C74 C76 C78 C80 C82 C84 C86-C88 C136 C205 = CAP-NP: CAP, CER, 1uF, 20%, 10V, X5R, 0201; Approved: Approved; CY_PN: 510-61183-01; Device_File: 510-61183-01; Dielectric: X5R; FPLIST: CAPC0603_0201N,CAPC0603_0201Q; Lifecycle: Active; Manufacturer: Murata; Manufacturer_PN: GRM033R61A105ME15D; Operating_Temp: -55°C ~ 85°C; Package: 0201; Part_Status: In prod; Tolerance: 20%; Voltage: 10V
FB1-FB7 = FB: IND, FERRITE BEAD, 600 OHM, 300mA, 1LN, 0402; Approved: Approved; CY_PN: 520-60353-01; Current: 300mA; DB_Status: Verified; Device_File: 520-60353-01; ESR: 600mOHM; FPLIST: INDC1005_0402M,INDC1005_0402N,INDC1005_0402L; Lifecycle: Active; Manufacturer: Würth Elektronik; Manufacturer_PN: 7427927291; Material: NA; Operating_Temp: -55°C ~ 125°C; Package: 0402; Part_Status: Unrel; Part_Type: Ferrite bead; Tolerance: NA
R102 = RES: RES, Fixed, 150 OHM, 1%, 1/10W, 0402; Approved: Approved; CY_PN: 500-60730-01; Device_File: 500-60730-01; FPLIST: RESC1005_0402N,RESC1005_0402M; Lifecycle: Active; Manufacturer: Wurth; Manufacturer_PN: 560112110061; Operating_Temp: -55°C ~ 155°C; Package: 0402; Part_Status: In Prod; Rating: 1/10W; Tolerance: 1%
TP21-TP25 TP53-TP56 TP70-TP72 = TP_SMD: TestPoint, PCB, Circle, 0.75mm, SMD; Approved: Approved; CY_PN: NA; DNI: DNI; Device_File: NA; Lifecycle: NA; Manufacturer: NA; Manufacturer_PN: NA; Part_Status: NA
U5 = IC_BGT60TR13C: IC, INFINEON, Radar Sensor, 60GHz, 1Tx 3Rx Antennas in Package, PG-VF2BGA40-1; Approved: Approved; Lifecycle: Active; Manufacturer: Infineon; Operating_Temp: -20 to +70°C; Operating_Voltage: 1.7V ~ 3.63V; Package: PG-VF2BGA40-1; Part_Status: Unrel
U24 = OSC-KC2016K: OSC, 80MHz, 50PPM, 1.6/3.63V, SMD; Approved: Approved; CY_PN: 540-60028-01; Device_File: 540-60028-01; Lifecycle: Active; Load_Capacitance: NA; Manufacturer: KYOCERA; Manufacturer_PN: KC2016K80.0000C1GE00; Operating_Temp: -40°C ~ 85°C; Output_Type: CMOS; Package: SMD; Part_Status: Unrel; Supply_Voltage: 1.6V ~ 3.63V; Tolerance: 50ppm
ANT1 = ANT_RFANT3216120A5T: ANTENNA, CHIP, 2.45/6.05 GHZ, SOLDER, SMD TRIBAND; Bands: 3; CY_PN: 753-60011-01; Description1: Tri band Chip antenna; Device_File: 753-60011-01; FPLIST: ANTENNA_2450AD18A6050,ANTENNA_2450AD18A6050_VER1; Frequency: 2.4GHz, 5GHz,6GHz; Frequency_Range: "2.4GHz - 2.48GHz, 5.15GHz - 5.85GHz / 5.85GHz-7.2GHz"; Gain: "2dBi / 1.5dBi / 2.7dBi"; Manufacturer: Johanson
C90 = CAP-NP: CAP, CER, 8.2pF, ± 0.10 pF, NP0, 50V, 0402; Approved: Approved; CY_PN: 510-60797-01; Description1: High Q, Low Loss; Device_File: 510-60797-01; Dielectric: NP0; FPLIST: CAPC1005_0402N,CAPC1005_0402M; Lifecycle: Active; Manufacturer: Johanson; Manufacturer_PN: 500R07S8R2BV4T; Operating_Temp: -55°C ~ 125°C; Package: 0402; Part_Status: In Prod; Tolerance: ± 0.1pF; Voltage: 50V
C91 = CAP-NP: CAP, CER, 2.7pF, ±0.1pF, C0G/NP0, 50V, 0402; Approved: Approved; CY_PN: 510-61221-01; Device_File: 510-61221-01; Dielectric: C0G/NP0; FPLIST: CAPC1005_0402N,CAPC1005_0402M; Lifecycle: Active; Manufacturer: Johanson Technology Inc.; Manufacturer_PN: QSCF500Q2R7B1GV001T; Operating_Temp: -55°C to 125°C; Package: 0402; Part_Status: Unrel; Tolerance: ±0.1pF; Voltage: 50V
C92 C94 C95 = CAP-NP: CAP, CER, 4.7uF, 20%, X5R, 10V, 0402; Approved: Approved; CY_PN: 510-60422-01; Device_File: 510-60422-01; Dielectric: X5R; FPLIST: CAPC1005_0402N,CAPC1005_0402M,capc1005_is0402q; Lifecycle: Active; Manufacturer: Murata; Manufacturer_PN: GRM155R61A475MEAAD; Operating_Temp: -55°C ~ 85°C; Package: 0402; Part_Status: In Prod; Tolerance: 20%; Voltage: 10V
C198 C199 = CAP-NP: CAP, CER, 8.2pF, ± 0.10 pF, NP0, 50V, 0402; Approved: Approved; CY_PN: 510-60797-01; DNI: DNI; Description1: High Q, Low Loss; Device_File: 510-60797-01; Dielectric: NP0; FPLIST: CAPC1005_0402N,CAPC1005_0402M; Lifecycle: Active; Manufacturer: Johanson; Manufacturer_PN: 500R07S8R2BV4T; Operating_Temp: -55°C ~ 125°C; Package: 0402; Part_Status: In Prod; Tolerance: ± 0.1pF; Voltage: 50V
C200 = CAP-NP: CAP, CER, 1UF, 20%, 10V, X5R, 0402; Approved: Approved; CY_PN: 510-60877-01; Device_File: 510-60877-01; Dielectric: X5R; FPLIST: CAPC1005_0402N,CAPC1005_0402M; Lifecycle: Active; Manufacturer: Wurth; Manufacturer_PN: 885012105012; Operating_Temp: -55°C ~ 85°C; Package: 0402; Part_Status: In Prod; Tolerance: 20%; Voltage: 10V
J12 = A-1JB: CONN, UMC, JACK, STR, 50 OHM, SMD; Approved: Approved; CY_PN: 720-60585-01; Conatct_Length: NA; Contact_Finish: GOLD; Current_Rating: NA; DNI: DNI; Device_File: 720-60585-01; Lifecycle: Active; Manufacturer: Amphenol; Mated_Height: NA; Operating_Temp: -40°C to 90°C; Part_Status: Unrel; Pin_Pitch: NA; Pins: 4; Row_pitch: NA; Rows: NA; Shrouding: NA
L2 L6 L7 = IND: IND, FIXED, uNSHIELDED, 3nH, ±0.1nH, 0.8A, 0.125 OHM, 0402; Approved: Approved; CY_PN: 520-60232-01; Current: 0.8A; DB_Status: Verified; DNI: DNI; Device_File: 520-60232-01; ESR: 0.125 OHM; FPLIST: INDC1005_0402M,INDC1005_0402N,INDC1005_0402L; Lifecycle: Active; Manufacturer: Murata; Manufacturer_PN: LQG15HS3N0B02D; Material: Unshielded; Operating_Temp: -55°C ~ 125°C; Package: 0402; Part_Status: In Des; Part_Type: Inductor; Tolerance: ±0.1nH
L3 = IND: IND, UNSHLD, 3.6nH, ±0.3nH, 0.3A, 0402; Approved: Approved; CY_PN: 520-60358-01; Current: 0.3A; DB_Status: Verified; Device_File: 520-60358-01; ESR: 210mOhm; FPLIST: INDC1005_0402M,INDC1005_0402N,INDC1005_0402L; Lifecycle: Active; Manufacturer: Johanson Technology Inc.; Manufacturer_PN: LRC0402CS3N6GV001T; Material: Unshielded; Operating_Temp: -55°C to 100°C; Package: 0402; Part_Status: Unrel; Part_Type: Inductor; Tolerance: ± 0.3 nH
L4 = IND: IND, FIXED, SHIELDED, 2.2uH, 20%, 2.6A, 135MOHM, 0806, SMD; Approved: Approved; CY_PN: 520-60354-01; Current: 2.6A; DB_Status: Verified; Device_File: 520-60354-01; ESR: 135mOHM; Lifecycle: Active; Manufacturer: Würth Elektronik; Manufacturer_PN: 74479276222C; Material: shielded; Operating_Temp: -40°C ~ 125°C; Package: 0806; Part_Status: Unrel; Part_Type: Inductor; Tolerance: ±20%
R103-R109 R112 R114 R123 R208 = RES: RES, 10K OHM, 1%, 1/20W, 0201; Approved: Approved; CY_PN: 500-61335-01; Device_File: 500-61335-01; FPLIST: RESC0603_0201N,RESC0603_0201Q; Lifecycle: Active; Manufacturer: Yageo; Manufacturer_PN: RC0201FR-0710KL; Operating_Temp: -55°C ~ 125°C; Package: 0201; Part_Status: In Des; Rating: 1/20W; Tolerance: 1%
R124 R153 R182 = RES: RES, FIXED, 0 OHM, JUMPER, 1A, 1/16W, 0402; Approved: Approved; CY_PN: 500-60344-01; Device_File: 500-60344-01; FPLIST: RESC1005_0402N,RESC1005_0402M; Lifecycle: Active; Manufacturer: Wurth; Manufacturer_PN: 560112110001; Operating_Temp: -55°C ~ 155°C; Package: 0402; Part_Status: In Prod; Rating: 1/16W; Tolerance: JUMPER
U25 = MOD_LBEE5HY2FY: IC, Module, CYW55513, 2.4GHz WLAN + Bluetooth, SMD; Approved: Approved; CY_PN: 460-60010-01; Device_File: 460-60010-01; Lifecycle: Active; Manufacturer: Murata; Operating_Temp: -40? to 85?; Operating_Voltage: 3.3V to 3.5V, 1.71V to 1.89V; Package: SMD; Part_Status: Unrel
Y4 = OSC-SiT1533: OSC, MEMS, 32.768kHz, 20ppm, LVCMOS, SMD; Approved: Approved; CY_PN: 540-60011-01; Description1: 2.00mm x 1.20mm x 0.55mm; Device_File: 540-60011-01; FPLIST: OSSCCC200X120X55-4N,OSCS4_SIT_2M0X1M2SPL_NGOPQ; Frequency_Stability: 100ppm; Lifecycle: Active; Load_Capacitance: NA; Manufacturer: SiTime; Operating_Temp: -40°C ~ 85°C; Output_Type: LVCMOS; Package: SMD; Part_Status: In Prod; Supply_Voltage: 1.2V - 3.63V; Tolerance: NA
C203 C204 = CAP-NP: CAP, CER, 1uF, 10%, X5R, 10V, 0402; CY_PN: 510-60276-01; Device_File: 510-60276-01; Dielectric: X5R; FPLIST: CAPC1005_0402N,CAPC1005_0402M; Lifecycle: Active; Manufacturer: TDK; Manufacturer_PN: CGB2A1X5R1A105K033BC; Operating_Temp: -55°C to 85°C; Package: 0402; Part_Status: In Prod; Tolerance: 10%; Voltage: 10V
J5 = PLG-6-J: CONN, HEADER, VERT, 6POS, 2.54MM, TH; Approved: Approved; CY_PN: 710-60054-01; Conatct_Length: 8.08mm; Contact_Finish: GOLD; Current_Rating: 3A; DNI: DNI; Device_File: 710-60054-01; Lifecycle: Active; Manufacturer: Sullins; Mated_Height: 10.58mm; Operating_Temp: -40°C ~ 105°C; Part_Status: Unrel; Pin_Pitch: 2.54mm; Pins: 6; Row_pitch: NA; Rows: 1; Shrouding: Unshrouded
J7 = PLG-4-2SH-J: CONN, HEADER, R/A, 4POS, 1MM, SMD; Approved: Approved; CY_PN: 720-60696-01; Conatct_Length: NA; Contact_Finish: Tin; Current_Rating: 1A; DNI: DNI; Device_File: 720-60696-01; Lifecycle: Active; Manufacturer: Wurth; Mated_Height: NA; Operating_Temp: -25°C ~ 85°C; Part_Status: In Des; Pin_Pitch: 1mm; Pins: 4; Row_pitch: NA; Rows: 1; Shrouding: Shrouded
J14 = SKT-20-ODD-EVEN-J: CONN, HDR, FEMALE, DUAL, 20POS, 2.54mm, GOLD, STR, TH; Approved: Approved; CY_PN: 720-60238-01; Conatct_Length: NA; Contact_Finish: GOLD; Current_Rating: 3A; Device_File: 720-60238-01; Lifecycle: Active; Manufacturer: Sullins; Manufacturer_PN: PPPC102LFBN-RC; Mated_Height: 8.5mm; Operating_Temp: -40°C to 105°C; Part_Status: In Prod; Pin_Pitch: 2.54mm; Pins: 20; Row_pitch: 2.54mm; Rows: 2; Shrouding: NA
J17 = PLG-20-ODD-EVEN-4SH-J: CONN, PLUG, DUAL, 20POS, 0.4mm, SMD, GOLD; Approved: Approved; CY_PN: 720-60640-01; Conatct_Length: NA; Contact_Finish: GOLD; Current_Rating: 0.3A; DNI: DNI; Device_File: 720-60640-01; Lifecycle: Active; Manufacturer: Hirose Electric Co Ltd; Mated_Height: 1.29mm; Operating_Temp: -35°C ~ +85°C; Part_Status: Unrel; Pin_Pitch: 0.4mm; Pins: 20; Row_pitch: NA; Rows: 2; Shrouding: Shrouded
R76 R77 R79 R80 = RES: RES, Fixed, 4.7K, 5%, 1/10W, 0603; Approved: Approved; CY_PN: 500-61354-01; DNI: DNI; Device_File: 500-61354-01; FPLIST: RESC1608_0603N,RESC1608_0603Q,RESC1608_0603M; Lifecycle: Active; Manufacturer: Wurth; Manufacturer_PN: 560112116045; Operating_Temp: -55°C ~ 155°C; Package: 0603; Part_Status: Unrel; Rating: 1/10W; Tolerance: 5%
R192-R195 = RES: RES, 100K OHM, 1%, 1/20W, 0201; Approved: Approved; CY_PN: 500-61334-01; Device_File: 500-61334-01; FPLIST: RESC0603_0201N,RESC0603_0201Q; Lifecycle: Active; Manufacturer: Yageo; Manufacturer_PN: RC0201FR-07100KL; Operating_Temp: -55°C ~ 125°C; Package: 0201; Part_Status: In Des; Rating: 1/20W; Tolerance: 1%
R204-R207 = RES: RES, 4.7K OHM, 5%, 1/20W, 0201; Approved: Approved; CY_PN: 500-60979-01; Device File: 500-60095-01; Device_File: 500-60979-01; FPLIST: RESC0603_0201N,RESC0603_0201Q; Lifecycle: Active; Manufacturer: Yageo; Manufacturer_PN: RC0201JR-074K7L; Operating_Temp: -55°C ~ 125°C; Package: 0201; Part_Status: Unrel; Rating: 1/20W; Tolerance: 5%
U40 = 74LVCH2T45GT: IC, Level Translator, N-INV, 2BIT, 1.2V-5.5V, 8-XSON; Approved: Approved; CY_PN: 450-60350-01; Description1: Bi-Directional, 3-state, Direction Control, Independent VCCA and VCCB, Partial Power Down; Device_File: 450-60350-01; FPLIST: SON50P100X200_08_SOT833-1,SON50P100X200X50-8N; Lifecycle: Active; Manufacturer: Nexperia; Operating_Temp: -40°C to 125°C; Operating_Voltage: 1.2V-5.5V, 1.2V-5.5V; Package: 8-XSON; Part_Status: Unrel
C96 C98 = CAP-NP: CAP, CER, 1uF, 20%, 10V, X5R, 0201; Approved: Approved; CY_PN: 510-61183-01; Device File: 510-60276-01; Device_File: 510-61183-01; Dielectric: X5R; FPLIST: CAPC0603_0201N,CAPC0603_0201Q; Lifecycle: Active; Manufacturer: Murata; Manufacturer_PN: GRM033R61A105ME15D; Operating_Temp: -55°C ~ 85°C; Package: 0201; Part Status: In Prod; Part_Status: In prod; Tolerance: 20%; Voltage: 10V
U3 = IC_S70KS1283GAB: IC, CYPRESS OCTAL RAM 1.8V IO 200Mhz 128Mb 24FBGA; Approved: Approved; Lifecycle: Active; Manufacturer: Infineon; Operating_Temp: -40°C to 85°C; Operating_Voltage: 1.7V - 2.0V; Package: 24FBGA; Part_Status: Unrel
U4 = IC_S25HS512TFABHI013: IC, INFINEON, FLASH, 512MBIT, SPI/QUAD, 24-BGA; Approved: Approved; Lifecycle: Active; Manufacturer: Infineon; Operating_Temp: -40°C ~ 85°C; Operating_Voltage: 1.7V ~ 2.0V; Package: 24-BGA; Part_Status: Unrel
C100 = CAP-NP: CAP, CER, 0.033uF, 10%, 10V, X5R, 0402; Approved: Approved; CY_PN: 510-60913-01; Device_File: 510-60913-01; Dielectric: X5R; FPLIST: CAPC1005_0402N,CAPC1005_0402M; Lifecycle: Active; Manufacturer: Murata; Manufacturer_PN: GRM155R61A333KA01D; Operating_Temp: -55°C ~ 85°C; Package: 0402; Part_Status: In Des; Tolerance: 10%; Voltage: 10V
C101 C103 = CAP-NP: CAP, CER, 22uF, 20%, X5R, 10V, 0402; Approved: Approved; CY_PN: 510-61184-01; Device_File: 510-61184-01; Dielectric: X5R; FPLIST: CAPC1005_0402N,CAPC1005_0402M; Lifecycle: Active; Manufacturer: Murata; Manufacturer_PN: GRM158R61A226ME15D; Operating_Temp: -55°C ~ 85°C; Package: 0402; Part_Status: Unrel; Tolerance: 20%; Voltage: 10V
J8 = PLG-2-J_SH1_2: CONN, HDR, MALE, R/A, 2POS, 1.25MM, SMD; Approved: Approved; CY_PN: 720-60753-01; Conatct_Length: NA; Contact_Finish: TIN; Current_Rating: 1A; DNI: DNI; Device_File: 720-60753-01; Lifecycle: Active; Manufacturer: Molex; Mated_Height: 3.4mm; Operating_Temp: -40°C to 105°C; Part_Status: Unrel; Pin_Pitch: 1.25mm; Pins: 2; Row_pitch: NA; Rows: 1; Shrouding: Shrouded
U28 = TLV320DAC3100: IC, AMP, STEREO DAC, CLASS-D, 2.5W, VQFN-32; Approved: Approved; CY_PN: 450-60436-01; Device_File: 450-60436-01; FPLIST: QFN50P500X500X100-32N_TP_NOFID,QFN50P500X500X100-32N_TP; Lifecycle: Active; Manufacturer: Texas Instruments; Manufacturer_PN: TLV320DAC3100IRHBR; Operating_Temp: -40??+85?; Operating_Voltage: 1.65V ~ 1.95V, 1.1V ~ 3.6V, 2.7V ~ 5.5V; Package: VQFN-32; Part_Status: In Des
C115 C122 C123 C130 = CAP-NP: CAP, CER, 0201, 10pF, 2%, 25V, C0G; Approved: Approved; CY_PN: 510-60964-01; DNI: DNI; Device_File: 510-60964-01; Dielectric: C0G; FPLIST: CAPC0603_0201N,CAPC0603_0201Q; Lifecycle: Active; Manufacturer: Murata; Manufacturer_PN: GRM0335C1E100GA01D; Operating_Temp: -55°C ~ 125°C; Package: 0201; Part_Status: Unrel; Tolerance: 2%; Voltage: 25V
C116 C121 C124 C129 = CAP-NP: CAP, CER, 12pF, 50V, 2%, C0G/NP0, 0201; Approved: Approved; CY_PN: 510-61194-01; Device_File: 510-61194-01; Dielectric: C0G/NP0; FPLIST: CAPC0603_0201N,CAPC0603_0201Q; Lifecycle: Active; Manufacturer: Murata; Manufacturer_PN: GRM0335C1H120GA01D; Operating_Temp: -55°C to 125°C; Package: 0201; Part_Status: In Design; Tolerance: 0.02; Voltage: 50V
C119 C127 = CAP-NP: CAP, CER, 390pF, 50V, 2%, C0G/NP0, 0201; Approved: Approved; CY_PN: 510-61195-01; Device_File: 510-61195-01; Dielectric: C0G/NP0; FPLIST: CAPC0603_0201N,CAPC0603_0201Q; Lifecycle: Active; Manufacturer: Murata; Manufacturer_PN: GRM0335C1H391GE01D; Operating_Temp: -55°C to 125°C; Package: 0201; Part_Status: In Design; Tolerance: 0.02; Voltage: 50V
R125 R126 R134 R135 = RES: RES, FIXED, 2.55M OHM, 1%, 1/20W, 0201; Approved: Approved; CY_PN: 500-61456-01; Device_File: 500-61456-01; FPLIST: RESC0603_0201N,RESC0603_0201Q; Lifecycle: Active; Manufacturer: Yageo; Manufacturer_PN: RC0201FR-072M55L; Operating_Temp: -55°C ~ 125°C; Package: 0201; Part_Status: In Design; Rating: 1/20W; Tolerance: 1%
R127 R128 R131 R132 R136 R137 R140 R141 = RES: RES, FIXED, 40.2K OHM, 1%, 1/20W, 0201; Approved: Approved; CY_PN: 500-61455-01; Device_File: 500-61455-01; FPLIST: RESC0603_0201N,RESC0603_0201Q; Lifecycle: Active; Manufacturer: Panasonic; Manufacturer_PN: ERJ-1GNF4022C; Operating_Temp: -55°C ~ 125°C; Package: 0201; Part_Status: In Design; Rating: 1/20W; Tolerance: 1%
R133 R142 = RES: RES, FIXED, 1.27M OHM, 1% 1/20W 0201; Approved: Approved; CY_PN: 500-61457-01; Device_File: 500-61457-01; FPLIST: RESC0603_0201N,RESC0603_0201Q; Lifecycle: Active; Manufacturer: Yageo; Manufacturer_PN: RC0201FR-071M27L; Operating_Temp: -55°C ~ 125°C; Package: 0201; Part_Status: In Design; Rating: 1/20W; Tolerance: 1%
R224 R227 R228 = RES: RES, FIXED, 0 OHM, JUMPER, 1A, 1/16W, 0402; Approved: Approved; CY_PN: 500-60344-01; DNI: DNI; Device_File: 500-60344-01; FPLIST: RESC1005_0402N,RESC1005_0402M; Lifecycle: Active; Manufacturer: Wurth; Manufacturer_PN: 560112110001; Operating_Temp: -55°C ~ 155°C; Package: 0402; Part_Status: In Prod; Rating: 1/16W; Tolerance: JUMPER
U9 U10 = IM73A135V01XTSA1: IC, INFINEON, Analog MEMS Microphone, IP57 dust and water resistant; Approved: Approved; Lifecycle: Active; Manufacturer: Infineon; Operating_Temp: -40°C to 85°C; Operating_Voltage: 1.52V~3V; Package: PG-LLGA-5-2; Part_Status: Unrel
J10 = SKT-15-2SH-J: CONN, FPC, TOP, RA, 15POS, 1MM, SMD; Approved: Approved; CY_PN: 720-60766-01; Conatct_Length: NA; Contact_Finish: GOLD; Current_Rating: 1A; Device_File: 720-60766-01; Lifecycle: Active; Manufacturer: Amphenol; Mated_Height: NA; Operating_Temp: -55°C ~ 105°C; Part_Status: Unrel; Pin_Pitch: 1.0mm; Pins: 15; Row_pitch: NA; Rows: 1; Shrouding: NA
J16 = PLG-4-ODD-EVEN-J: CONN, HDR, MALE, 4 POS, 2.54 MM, GOLD, RA, SMD; Approved: Approved; CY_PN: 720-60764-01; Conatct_Length: 5.84mm; Contact_Finish: GOLD; Current_Rating: 4.1A; DNI: DNI; Device_File: 720-60764-01; Lifecycle: Active; Manufacturer: Samtec; Mated_Height: NA; Operating_Temp: -55°C ~ 125°C; Part_Status: Unrel; Pin_Pitch: 2.54mm; Pins: 4; Row_pitch: 4.19mm; Rows: 2; Shrouding: NA

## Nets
GND_SIGNAL: C62.2 C63.1 C64.2 C65.2 C66.2 C67.2 C68.2 C69.2 C70.2 C71.2 C72.1 C73.2 C74.2 C75.2 C76.2 C77.2 C78.2 C79.2 C80.2 C81.2 C82.2 C83.2 C84.2 C85.2 C86.2 C87.2 C88.2 C89.2 C92.2 C93.2 C94.2 C95.2 C96.2 C97.2 C98.2 C99.2 C100.2 C101.2 C102.2 C103.2 C104.2 C107.2 C108.2 C109.2 C110.2 C111.2 C112.2 C113.2 C114.2 C115.2 C116.2 C118.2 C123.2 C124.2 C126.2 C136.2 C200.2 C203.1 C204.2 C205.2 J5.6 J7.1 J7.SH1 J7.SH2 J8.SH1 J8.SH2 J10.3 J10.6 J10.9 J10.12 J10.15 J10.SH1 J10.SH2 J12.G1(GND) J12.G2(GND) J12.G3(GND) J14.20 J16.3 J17.4 J17.SH1 J17.SH2 J17.SH3 J17.SH4 L2.1 L3.1 L6.1 L7.1 R77.2 R80.2 R84.2 R86.2 R110.1 R126.1 R135.1 R216.2 U3.B3(VSS) U3.C1(VSSQ_1) U3.E5(VSSQ_2) U4.B3(VSS) U5.A1(VSSD_1) U5.A2(VSSD_2) U5.A3(VSSRF_20) U5.A4(VSSRF_18) U5.A5(VSSRF_16) U5.A6(VSSRF_15) U5.A7(VSSRF_14) U5.A8(VSSRF_13) U5.A9(VSSRF_12) U5.B3(VSSRF_19) U5.B4(VSSRF_17) U5.B8(VSSRF_11) U5.B9(VSSRF_10) U5.C9(VSSRF_9) U5.D9(VSSRF_8) U5.E9(VSSRF_7) U5.H9(VSSRF_6) U5.J9(VSSRF_5) U5.K1(VSSA) U5.K9(VSSRF_4) U5.L9(VSSRF_3) U5.M7(VSSRF_1) U5.M9(VSSRF_2) U6.1(GND) U6.7(GND) U7.5(GND) U8.4(LR) U8.5(GND) U9.4(GND1) U9.5(GND2) U10.4(GND1) U10.5(GND2) U18.6(GNDIO) U18.7(GND) U20.B1(GND) U20.C3(BYPASS) U22.4(VSS) U24.2(GND) U25.10(GND) U25.12(GND) U25.13(GND) U25.19(GND) U25.21(GND) U25.24(PVSSA) U25.26(PVSSA) U25.27(PVSSA) U25.29(GND) U25.39(GND) U25.44(GND) U25.49(GND) U25.51(GND) U25.52(GND) U25.53(GND) U25.55(GND) U25.56(GND) U25.58(GND) U25.59(GND) U25.60(GND) U25.61(GND) U25.66(GND) U25.67(GND) U25.68(GND) U25.69(GND) U25.70(GND) U25.71(GND) U25.72(GND) U28.1(IOVSS) U28.16(AVSS) U28.18(DVSS) U28.20(SPKVSS) U28.25(SPKVSS) U28.29(HPVSS) U28.H(EPAD) U40.4(GND) Y4.G(GND) ; also on sheet 5 6 7 8 9 20 21
VCC_1V8: C73.1 C75.1 C81.1 C83.1 C89.1 FB1.1 FB2.1 FB4.1 FB5.1 FB6.1 FB7.1 J17.3 R124.1 ; also on sheet 7 21
VCC_3V3: C77.1 FB3.1 J17.2 ; also on sheet 7
VDD_1V8: C62.1 C63.2 C64.1 C65.1 C66.1 C67.1 C68.1 C70.1 C71.1 C96.1 C97.1 C98.1 C99.1 C111.1 C112.1 C113.1 C114.1 C200.1 C204.1 J5.1 R76.1 R79.1 R85.2 R112.2 R114.2 R123.2 R192.2 R193.2 R194.2 R195.2 R203.2 R204.1 R205.1 R208.2 R224.1 U3.B4(VCC) U3.D1(VCCQ_2) U3.E4(VCCQ_1) U4.B4(VCC) U6.6(VDDIO) U6.8(VDD) U7.2(VDD) U7.4(LR) U8.2(VDD) U18.5(VDDIO) U18.8(VDD) U18.12(CSB) U20.B2(ADSEL) U20.B3(VDDIO) U20.C1(VDD) U22.3(VDD) U28.2(IOVDD) U28.3(DVDD) U40.8(VCCB) Y4.P(VDD) ; also on sheet 5 6 7 9 21
VDD_3V3: C94.1 C95.1 C107.1 C108.1 C109.1 C110.1 C203.2 J7.2 J14.19 R153.2 R206.2 R207.2 R217.2 U25.22(VBAT_SR) U25.23(VBAT_SR) U28.17(AVDD) U28.28(HPVDD) U40.1(VCCA) ; also on sheet 6 7 9 21
VDD_5V: C101.1 C102.1 C103.1 C104.1 C205.1 J16.1 J17.1 U28.21(SPKVDD_1) U28.24(SPKVDD_2) ; also on sheet 5 6 7 9
VDDA_RADAR: C76.1 FB2.2 U5.J1(VDDA)
VDDD_RADAR: C74.1 FB1.2 U5.H1(VDDD)
VDDIO_RADIO: C93.1 R103.1 R104.1 R105.1 R106.1 R107.1 R108.1 R109.1 R203.1 U25.11(VDDIO)
VDDLF_RADAR: C78.1 FB3.2 U5.M3(VDDLF)
VDDPLL_RADAR: C84.1 FB6.2 U5.M4(VDDPLL)
VDDRF_RADAR: C85.1 C86.1 C87.1 C88.1 FB7.2 U5.F9(VDDRF_2) U5.G9(VDDRF_3) U5.M1(VDDRF_1)
VDDVCO_RADAR: C82.1 FB5.2 U5.M6(VDDVCO)
A_IO_P13_0: J17.20 ; also on sheet 19
A_IO_P13_1: J17.18 ; also on sheet 19
A_IO_P13_2: J17.16 ; also on sheet 19
A_IO_P13_3: J17.14 ; also on sheet 19
A_IO_P13_4: J17.12 ; also on sheet 19
A_IO_P13_5: J17.10 ; also on sheet 19
A_IO_P13_6: J17.8 ; also on sheet 19
A_IO_P13_7: J17.6 ; also on sheet 19
A_IO_P15_0: J17.5 ; also on sheet 19
A_IO_P15_1: J17.7 ; also on sheet 19
A_IO_P15_2: J17.9 ; also on sheet 19
A_IO_P15_3: J17.11 ; also on sheet 19
A_IO_P15_4: J17.13 ; also on sheet 19
A_IO_P15_5: J17.15 ; also on sheet 19
A_IO_P15_6: J17.17 ; also on sheet 19
A_IO_P15_7: J17.19 ; also on sheet 19
ALT_SER_INT_CONFIG_1: R76.2 R77.1 ; also on sheet 19
ALT_SER_INT_CONFIG_2: R79.2 R80.1 ; also on sheet 19
AMIC1_CTB_INN: C121.2 R132.2 ; also on sheet 19
AMIC1_CTB_INP: C116.1 R128.2 R227.2 ; also on sheet 19
AMIC1_CTB_OUT: C121.1 C122.1 R133.2 ; also on sheet 19
AMIC1_CTB_REF: R227.1 ; also on sheet 19
AMIC2_CTB_INN: C129.2 R141.2 ; also on sheet 19
AMIC2_CTB_INP: C124.1 R137.2 R228.2 ; also on sheet 19
AMIC2_CTB_OUT: C129.1 C130.1 R142.2 ; also on sheet 19
AMIC2_CTB_REF: R228.1 ; also on sheet 19
AMIC_1V8: C118.1 C126.1 R124.2 R125.1 R134.1 R224.2 U9.2(VDD) U10.2(VDD)
BT_DEV_WAKE: R106.2 U25.40(LHL_GPIO_0) ; also on sheet 19
BT_HOST_WAKE: R107.2 U25.41(BT_HOST_WAKE) ; also on sheet 19
BT_REG_ON: R105.2 U25.8(BT_REG_ON) ; also on sheet 19
BT_UART_CTS_MCU_RTS: TP55.1(TP) U25.48(BT_UART_CTS_N) ; also on sheet 19
BT_UART_RTS_MCU_CTS: TP56.1(TP) U25.47(BT_UART_RTS_N) ; also on sheet 19
BT_UART_RX_MCU_TX: TP53.1(TP) U25.45(BT_UART_RXD) ; also on sheet 19
BT_UART_TX_MCU_RX: TP54.1(TP) U25.46(BT_UART_TXD) ; also on sheet 19
DISP_VDD_3V3: C136.1 J10.1 J10.2 R153.1
DSI_CLK_N: J10.11 ; also on sheet 19
DSI_CLK_P: J10.10 ; also on sheet 19
DSI_DATA0_N: J10.8 ; also on sheet 19
DSI_DATA0_P: J10.7 ; also on sheet 19
DSI_DATA1_N: J10.14 ; also on sheet 19
DSI_DATA1_P: J10.13 ; also on sheet 19
I2C_SCL_1V8: R223.2 U6.4(SCK) U18.13(SCX) U22.2(SCL) U28.10(SCL) ; also on sheet 8 19
I2C_SCL_3V3: J7.4 J10.5 J14.17 J16.2 R207.1 ; also on sheet 19
I2C_SDA_1V8: R220.2 U6.3(SDI) U18.14(SDX) U22.1(SDA) U28.9(SDA) ; also on sheet 8 19
I2C_SDA_3V3: J7.3 J10.4 J14.18 J16.4 R206.1 ; also on sheet 19
I2S_TX_FSYNC: U28.6(WCLK) ; also on sheet 19
I2S_TX_MCK: U28.8(MCLK) ; also on sheet 19
I2S_TX_SCK: U28.7(BCLK) ; also on sheet 19
I2S_TX_SD: U28.5(DIN) ; also on sheet 19
I3C_SCL: R205.2 R222.2 TP71.1(TP) ; also on sheet 19
I3C_SDA: R204.2 R221.2 TP72.1(TP) ; also on sheet 19
IMU_INT1: U18.4(INT1) ; also on sheet 19
IMU_INT2: U18.9(INT2) ; also on sheet 19
JTAG_SEL: R109.2 R110.2 U25.57(JTAG_SEL)
LPO_OUT_2FY: R182.2 U25.30(LPO_IN)
MAG_INT: U20.A1(INT) ; also on sheet 19
MEMORY_RST: R208.1 U3.A4(RESET#) ; also on sheet 19
P11_1: TP70.1(TP) U40.7(1B) ; also on sheet 19
P11_1_IN_3V3: J14.13 U40.2(1A)
P16_0: J14.6 ; also on sheet 19
P16_1: J14.5 ; also on sheet 19
P16_2: J14.8 ; also on sheet 19
P16_3: J14.7 ; also on sheet 19
P16_4: J14.10 ; also on sheet 19
P16_5: J14.9 ; also on sheet 19
P16_6: J14.12 ; also on sheet 19
P16_7: J14.11 ; also on sheet 19
P17_2: J14.15 ; also on sheet 19
P17_3: J14.16 ; also on sheet 19
P17_4: J14.14 ; also on sheet 19
P17_5: J14.1 J14.3 ; also on sheet 19
P17_7: J14.2 J14.4 ; also on sheet 19
PDM_CLK: R88.2 R92.2 ; also on sheet 19
PDM_DATA: R87.2 R91.2 ; also on sheet 19
PSEN_INT: R84.1 U6.5(SDO) ; also on sheet 19
RF_OUT: C90.1 C198.1 U25.50(ANT)
ROSC_IN_80MHz: R102.2 U5.M2(OSC)
RSPI_CLK: U5.B1(CLK) ; also on sheet 19
RSPI_CS: U5.G1(CS) ; also on sheet 19
RSPI_IRQ: U5.C1(IRQ) ; also on sheet 19
RSPI_MISO: U5.E1(DO) ; also on sheet 19
RSPI_MOSI: U5.D1(DI) ; also on sheet 19
RXRES_L: R101.1 ; also on sheet 19
SERIAL_INT0: J5.5 R192.1 ; also on sheet 19
SERIAL_INT1: J5.4 R193.1 ; also on sheet 19
SERIAL_INT2: J5.3 R194.1 ; also on sheet 19
SERIAL_INT3: J5.2 R195.1 ; also on sheet 19
SMIF0_CLKP: U4.B2(CK) ; also on sheet 19
SMIF0_CS: R112.1 U4.C2(\~{CS}) ; also on sheet 19
SMIF0_DATA0: U4.D3(DQ0/SI) ; also on sheet 19
SMIF0_DATA1: U4.D2(DQ1/SO) ; also on sheet 19
SMIF0_DATA2: U4.C4(DQ2~{/WP}) ; also on sheet 19
SMIF0_DATA3: U4.D4(DQ3~{/RESET}) ; also on sheet 19
SMIF1_CLKN: U3.B1(CK#) ; also on sheet 19
SMIF1_CLKP: U3.B2(CK) ; also on sheet 19
SMIF1_CS: R114.1 U3.A3(CS#) ; also on sheet 19
SMIF1_DATA0: U3.D3(DQ0) ; also on sheet 19
SMIF1_DATA1: U3.D2(DQ1) ; also on sheet 19
SMIF1_DATA2: U3.C4(DQ2) ; also on sheet 19
SMIF1_DATA3: U3.D4(DQ3) ; also on sheet 19
SMIF1_DATA4: U3.D5(DQ4) ; also on sheet 19
SMIF1_DATA5: U3.E3(DQ5) ; also on sheet 19
SMIF1_DATA6: U3.E2(DQ6) ; also on sheet 19
SMIF1_DATA7: U3.E1(DQ7) ; also on sheet 19
SMIF1_RWDS: U3.C3(RWDS) ; also on sheet 19
WL_BT_DEV_WAKE: R103.2 U25.5(LHL_GPIO_1) ; also on sheet 19
WL_HOST_WAKE: R104.2 U25.2(GPIO_0) ; also on sheet 19
WL_REG_ON: R108.2 U25.9(WL_REG_ON) ; also on sheet 19
WL_SDIO_CLK: U25.20(SDIO_CLK) ; also on sheet 19
WL_SDIO_CMD: U25.15(SDIO_CMD) ; also on sheet 19
WL_SDIO_DATA0: U25.14(SDIO_DATA0) ; also on sheet 19
WL_SDIO_DATA1: U25.16(SDIO_DATA1) ; also on sheet 19
WL_SDIO_DATA2: U25.17(SDIO_DATA2) ; also on sheet 19
WL_SDIO_DATA3: U25.18(SDIO_DATA3) ; also on sheet 19
N17461053: TP21.1(TP) U5.M5(DIV)
N17461288: C72.2 U5.L1(VAREF)
N17462113: C79.1 C80.1 FB4.2 U24.4(VCC)
N17462137: R102.1 U24.3(OUTPUT)
N17506591: R85.1 R86.1 U18.1(SDO)
N17604769: R101.2 U5.F1(RST)
N17691977: C92.1 L4.1 U25.25(ABUCK_1P12_IN)
N17691999: L4.2 U25.28(ABUCK_1P12_OUT)
N17694386: J8.1 U28.22(SPKP_1) U28.26(SPKP_2)
N17694402: J8.2 U28.19(SPKM_1) U28.23(SPKM_2)
N17694449: C100.1 R123.1 U28.31(\~{RESET})
N17694464: TP22.1(TP) U28.27(HPL)
N17694501: TP23.1(TP) U28.30(HPR)
N17694590: C105.1 TP24.1(TP)
N17694592: C105.2 U28.13(AIN1)
N17694611: C106.2 U28.14(AIN2)
N17694617: C106.1 TP25.1(TP)
N17695662: C115.1 C119.1 R125.2 R126.2 R127.2 R128.1
N17695725: C117.2 R127.1
N17695747: R129.1 U10.1(OUTPUT_P)
N17695749: C117.1 R129.2
N17695799: R130.1 U10.3(OUTPUT_N)
N17695801: C120.1 R130.2
N17695803: C120.2 R131.1
N17695815: C119.2 C122.2 R131.2 R132.1 R133.1
N17695981: C123.1 C127.1 R134.2 R135.2 R136.2 R137.1
N17696044: C125.2 R136.1
N17696066: R138.1 U9.1(OUTPUT_P)
N17696068: C125.1 R138.2
N17696118: R139.1 U9.3(OUTPUT_N)
N17696120: C128.1 R139.2
N17696122: C128.2 R140.1
N17696134: C127.2 C130.2 R140.2 R141.1 R142.1
N17920449: ANT1.1 C91.2 L3.2
N17920453: C90.2 C91.1 L2.2
N17920674: C198.2 C199.1 L6.2
N17920680: C199.2 J12.S(SIG) L7.2
N17947353: R182.1 Y4.O(OUT)
N17989965: R88.1 U8.3(CLOCK)
N17989977: R87.1 U8.1(DATA)
N17990624: R92.1 U7.3(CLOCK)
N17990639: R91.1 U7.1(DATA)
N18042757: R216.1 R217.1 U40.5(DIR)
N18094677: R220.1 R221.1 U20.A2(SDA)
N18094686: R222.1 R223.1 U20.A3(SCK)
N18095156: C69.1 U20.C2(CRST)

Not connected (* = marked no-connect by the designer): ANT1 2*; U3 A2(RFU_2)* A5(RFU_3)* B5(RFU_4)* C2(RFU_1)* C5(RFU_5)*; U4 A2(DNU1)* A3(DNU2)* A4(\~{RESET})* A5(DNU3)* B1(DNU4)* B5(DNU5)* C1(DNU6)* C3(DNU7)* C5(DNU8)* D1(DNU9)* D5(DNU10)* E1(DNU11)* E2(DNU12)* E3(DNU13)* E4(DNU14)* E5(DNU15)*; U6 2(CSB)*; U18 2(ASDx)* 3(ASCx)* 10(OCSB)* 11(OSDO)*; U24 1(STAND-BY-FUNC)*; U25 1(GPIO_6)* 3(GPIO)* 4(GPIO_5)* 6(GPIO_4)* 7(GPIO_2)* 31(TDM2_MCK)* 32(BT_PCM_IN)* 33(BT_PCM_SYNC)* 34(BT_PCM_OUT)* 35(BT_PCM_CLK)* 36(I2S_DO)* 37(I2S_CLK)* 38(I2S_WS)* 42(I2S_DI)* 43(TDM1_MCK)* 54(NC)* 62(BT_GPIO_4)* 63(BT_GPIO_3)* 64(BT_GPIO_2)* 65(BT_GPIO_5)*; U28 4(NC_1)* 11(VOL/MICDET)* 12(MICBIAS)* 15(NC_2)* 32(GPIO1)*; U40 3(2A)* 6(2B)*; Y4 N(NC)*

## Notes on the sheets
sheet 10
- Digital Barometric Pressure Sensor
- 6-axis IMU (Accelerometer + Gyroscope)
- NOTE:
- R84 is open I2C address is
  0x77, if loaded then 0x76
- NOTE:
- If SDO=0, I2C address is 0x68 (Default)
  If SDO=1, I2C address is 0x69
- Digital MEMS Microphone 1
- Digital Humidity Sensor
- NOTE:
- PDM DATA is available on
  Logic LOW of Clock signal
- Digital MEMS Microphone 2
- I2C Slave Address: 0x44
- 3-axis Magnetometer
- NOTE:
- PDM DATA is available on
  Logic HIGH of Clock signal
- NOTE:
- I2C Slave Address: 0x15
sheet 11
- BGT60TR13C RADAR Sensor
- Supply for RADAR Sensor
- Crystal Oscillator - RADAR Clock Source
sheet 12
- Onboard Hatchet-1 2FY Radio
- Onboard LPO
- 32.768KHz
sheet 13
- Expansion IO Header
- QWIIC interface
- Alternative Serial Interface Configuration
- PCLK Level translator
- Analog Expansion IO connector
- Make Y-connection
- Make Y-connection
- R76, R77: DNI
- R76: MOUNT; R77: DNI
- R76: DNI; R77: MOUNT
- R79, R80: DNI
- N/A*
- N/A*
- N/A*
- R79: MOUNT; R80: DNI
- RFU**
- UART
- RFU**
- R79: DNI; R80: MOUNT
- SPI
- I2C
- SPI
- * This feature is not supported on this board.
- NOTE:
- ** RFU: Reserved for future use
- Alternate serial interface is not supported by default.
- Make Y-connection
sheet 14
- Hyper Bus/Octal PSRAM
- QSPI Flash Memory
sheet 15
- Audio Class-D Amplifier
- I2C Slave Address: 0x18
sheet 16
- Analog MICs
sheet 17
- MIPI-DSI R-Pi Compatible Display Interface
- D1N
- D1P
- CLKN
- CLKP
- D0N
- D0P
- SCL
- SDA
- 3.3V
- 3.3V
